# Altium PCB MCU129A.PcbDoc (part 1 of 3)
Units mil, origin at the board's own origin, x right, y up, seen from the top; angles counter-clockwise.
Board outline 3092.79 x 1702.62 mil, 4 copper layers (Top Layer, L2_GND, L3_PWR/SIG, Bottom Layer), stack 58.736 mil thick; 213 components, 108 nets, 914 pads, 219 vias.
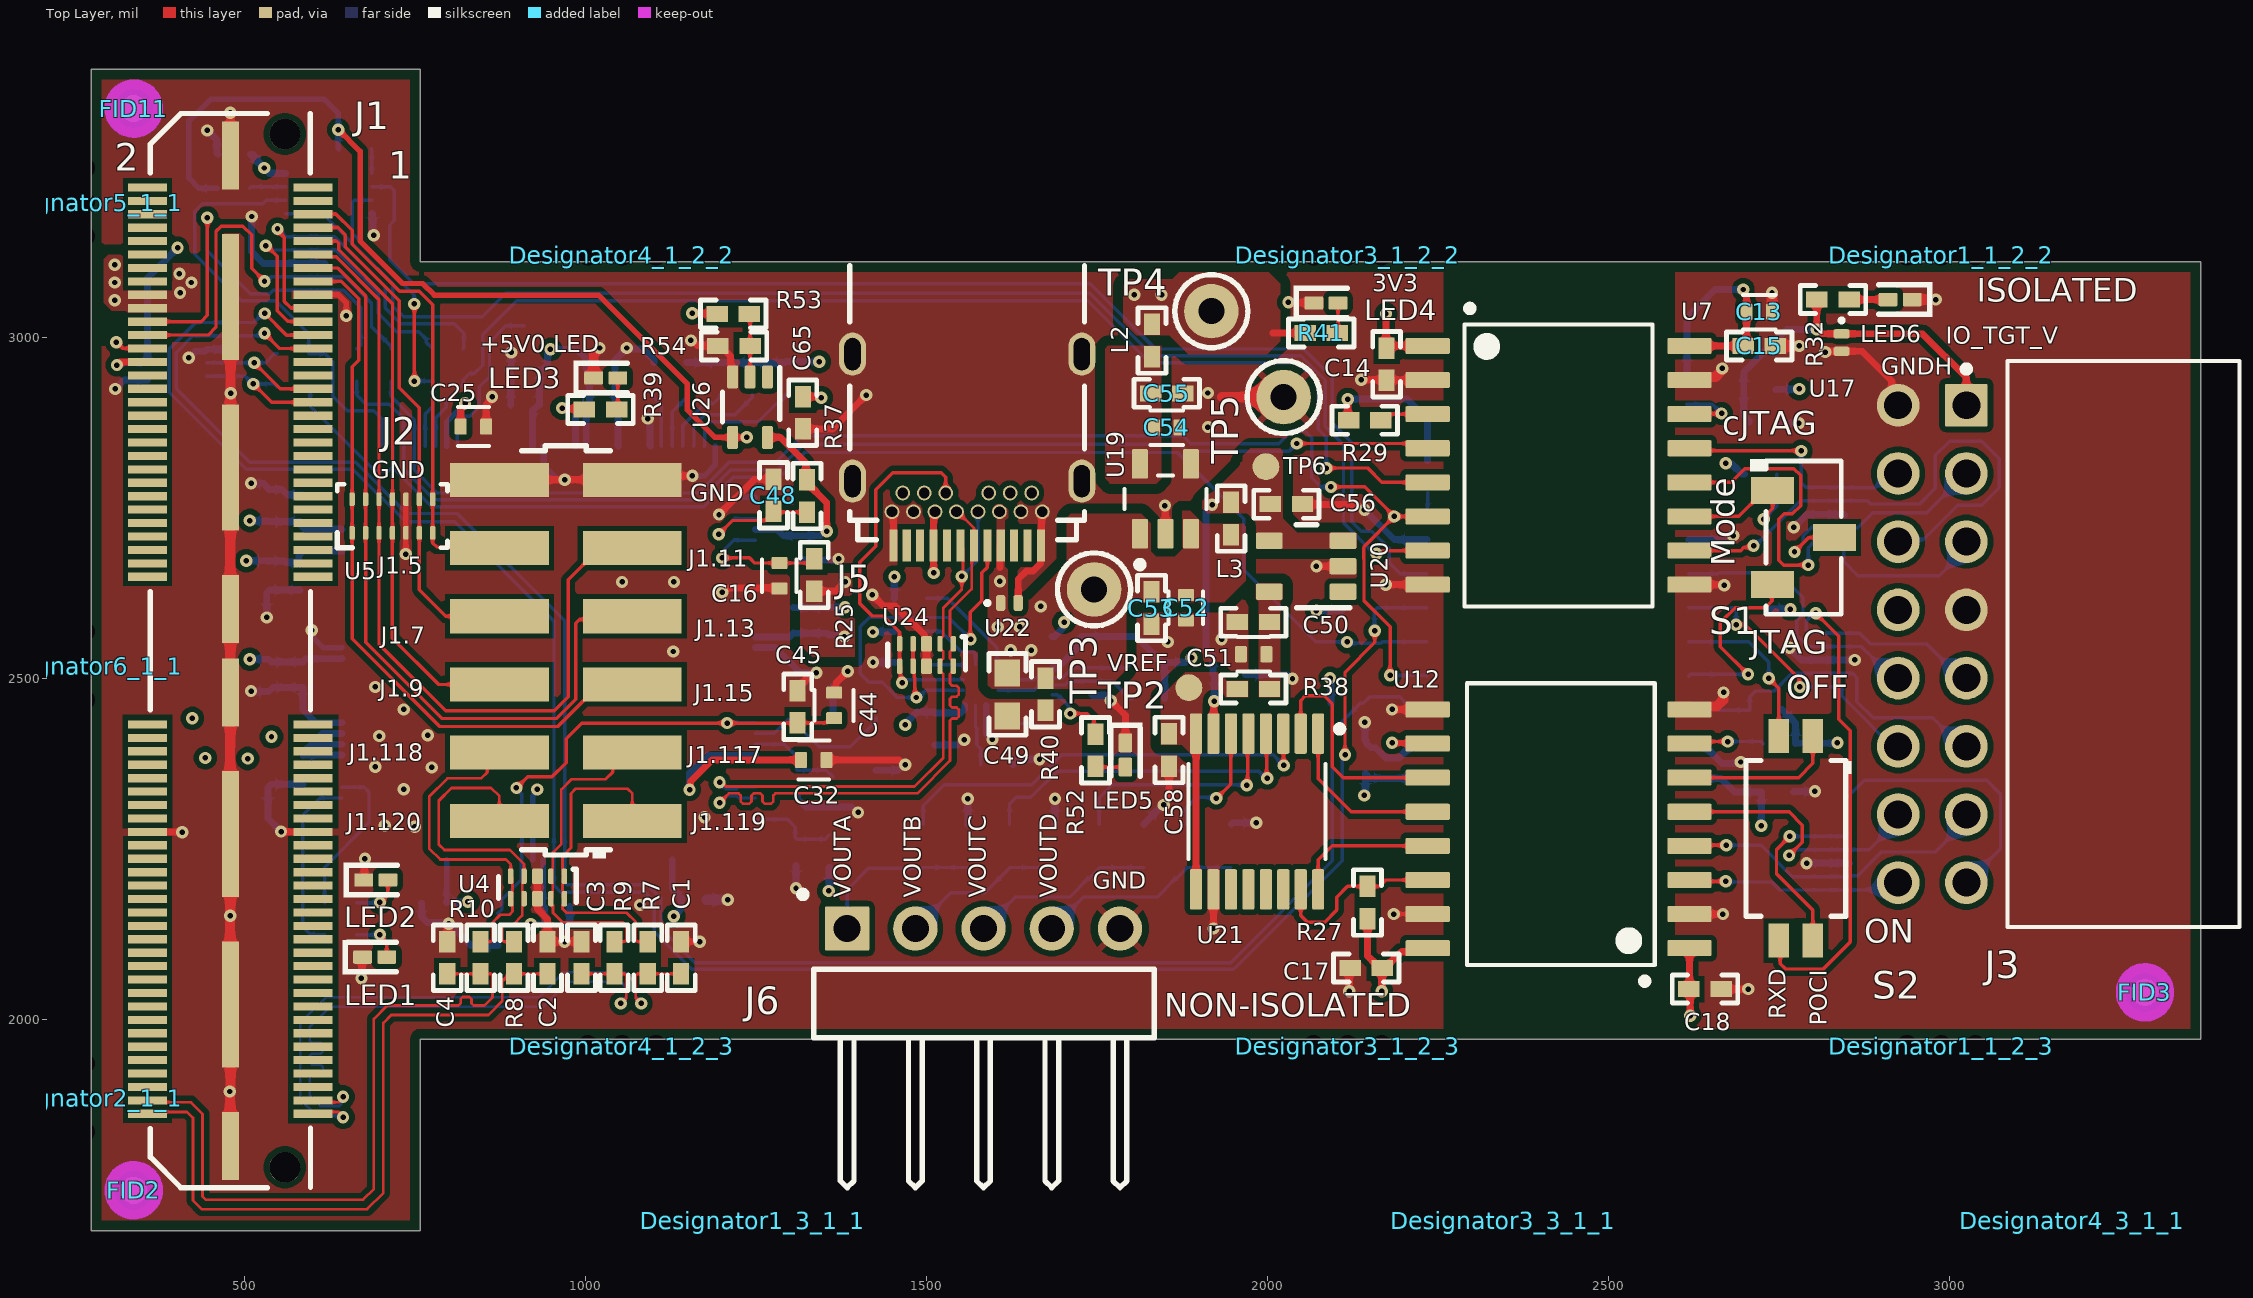
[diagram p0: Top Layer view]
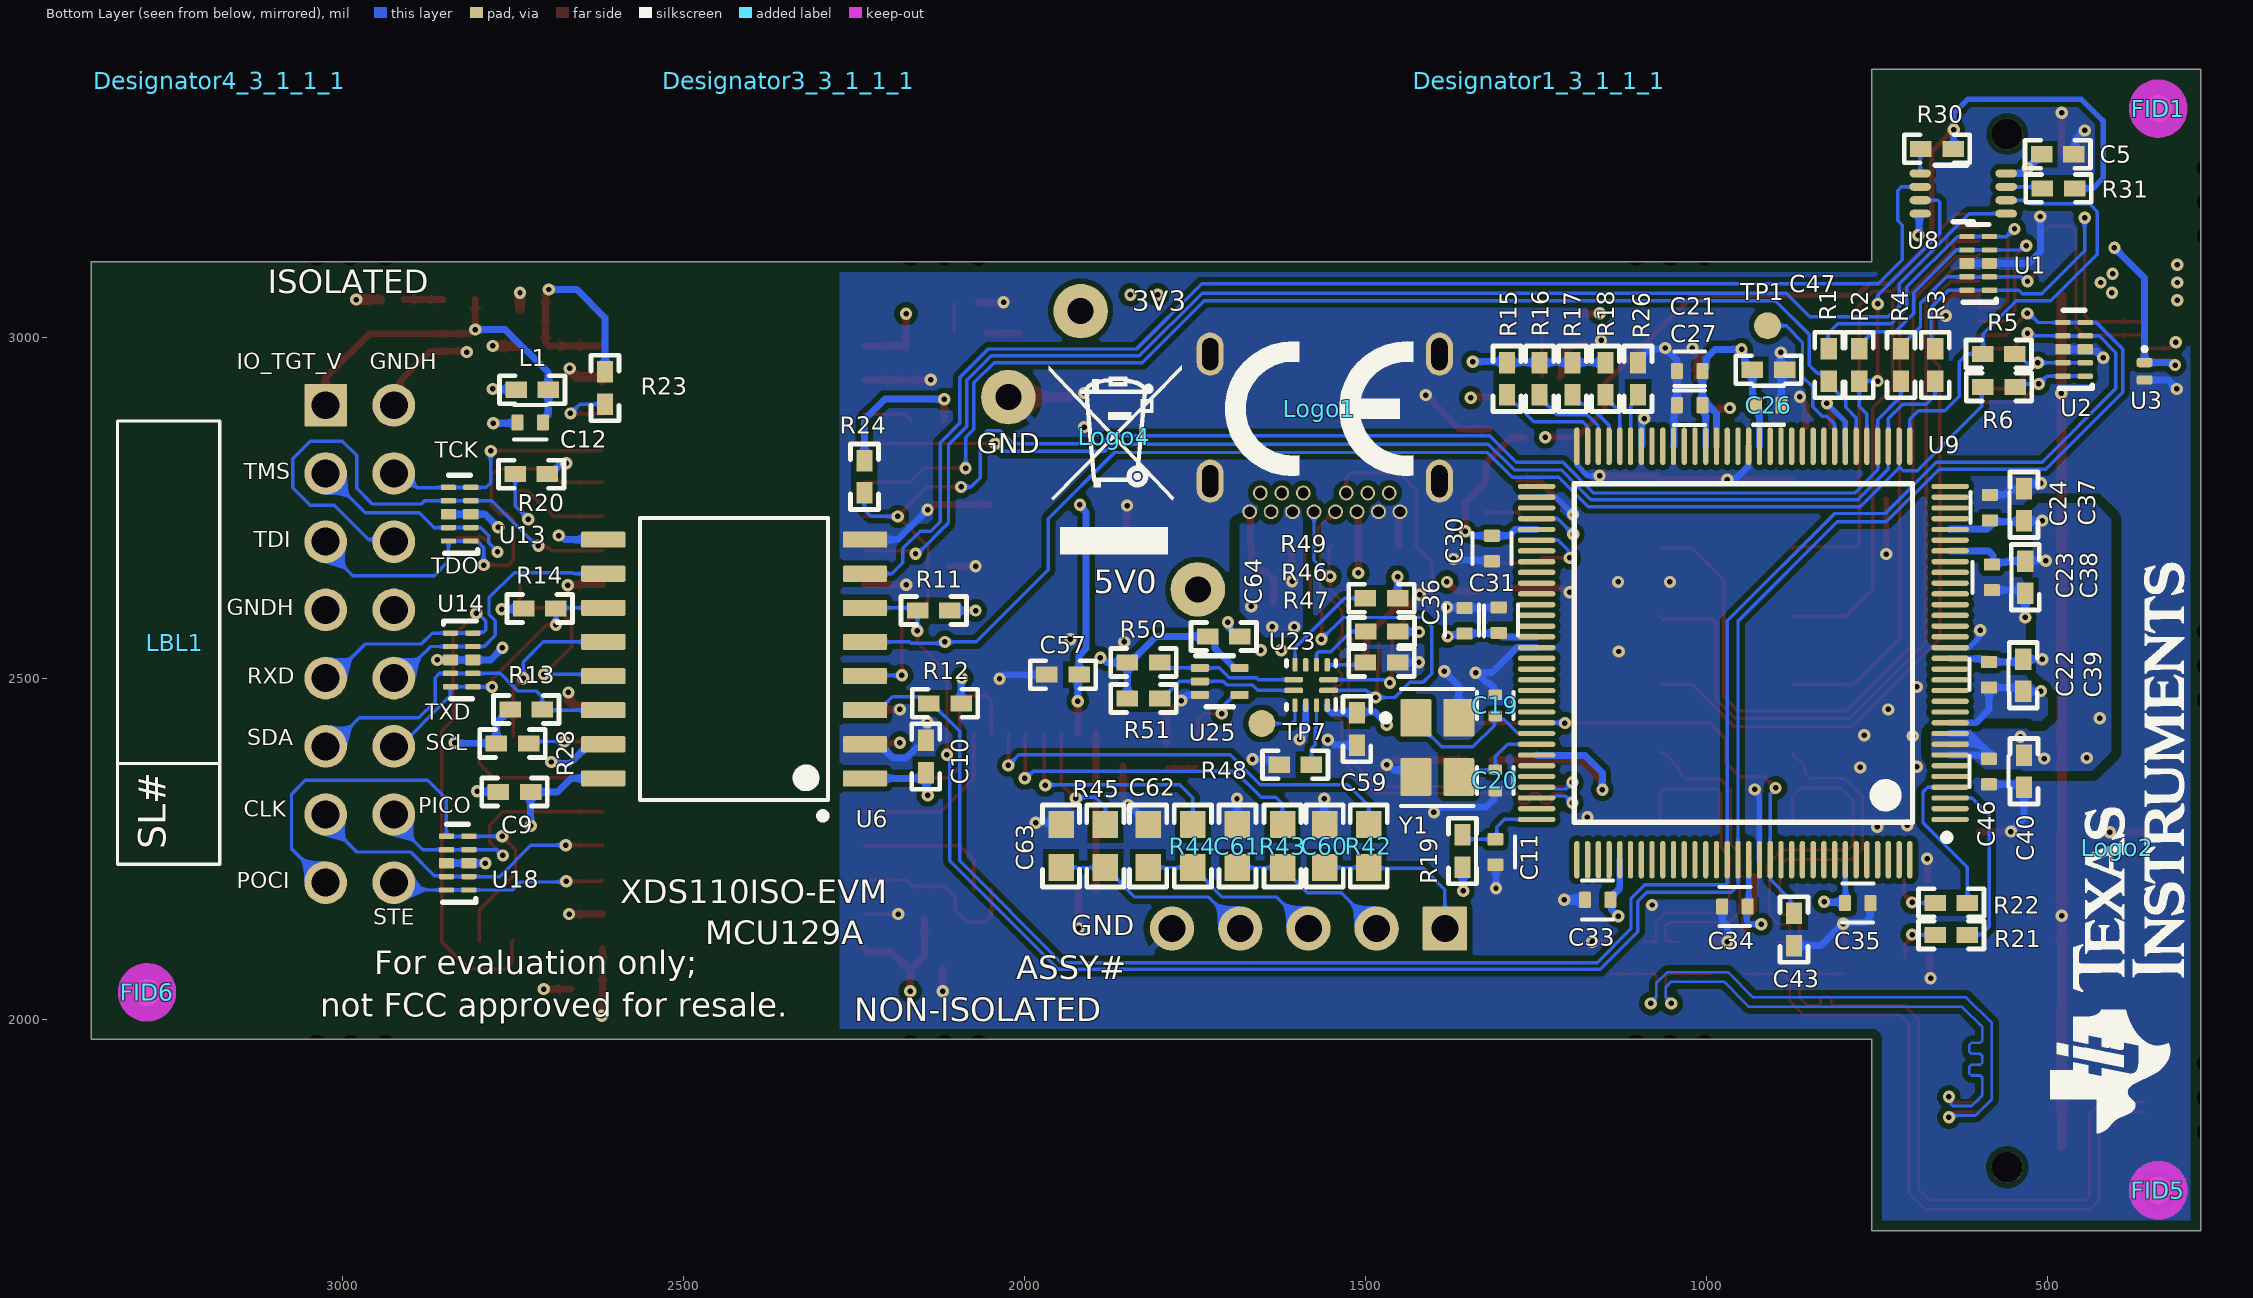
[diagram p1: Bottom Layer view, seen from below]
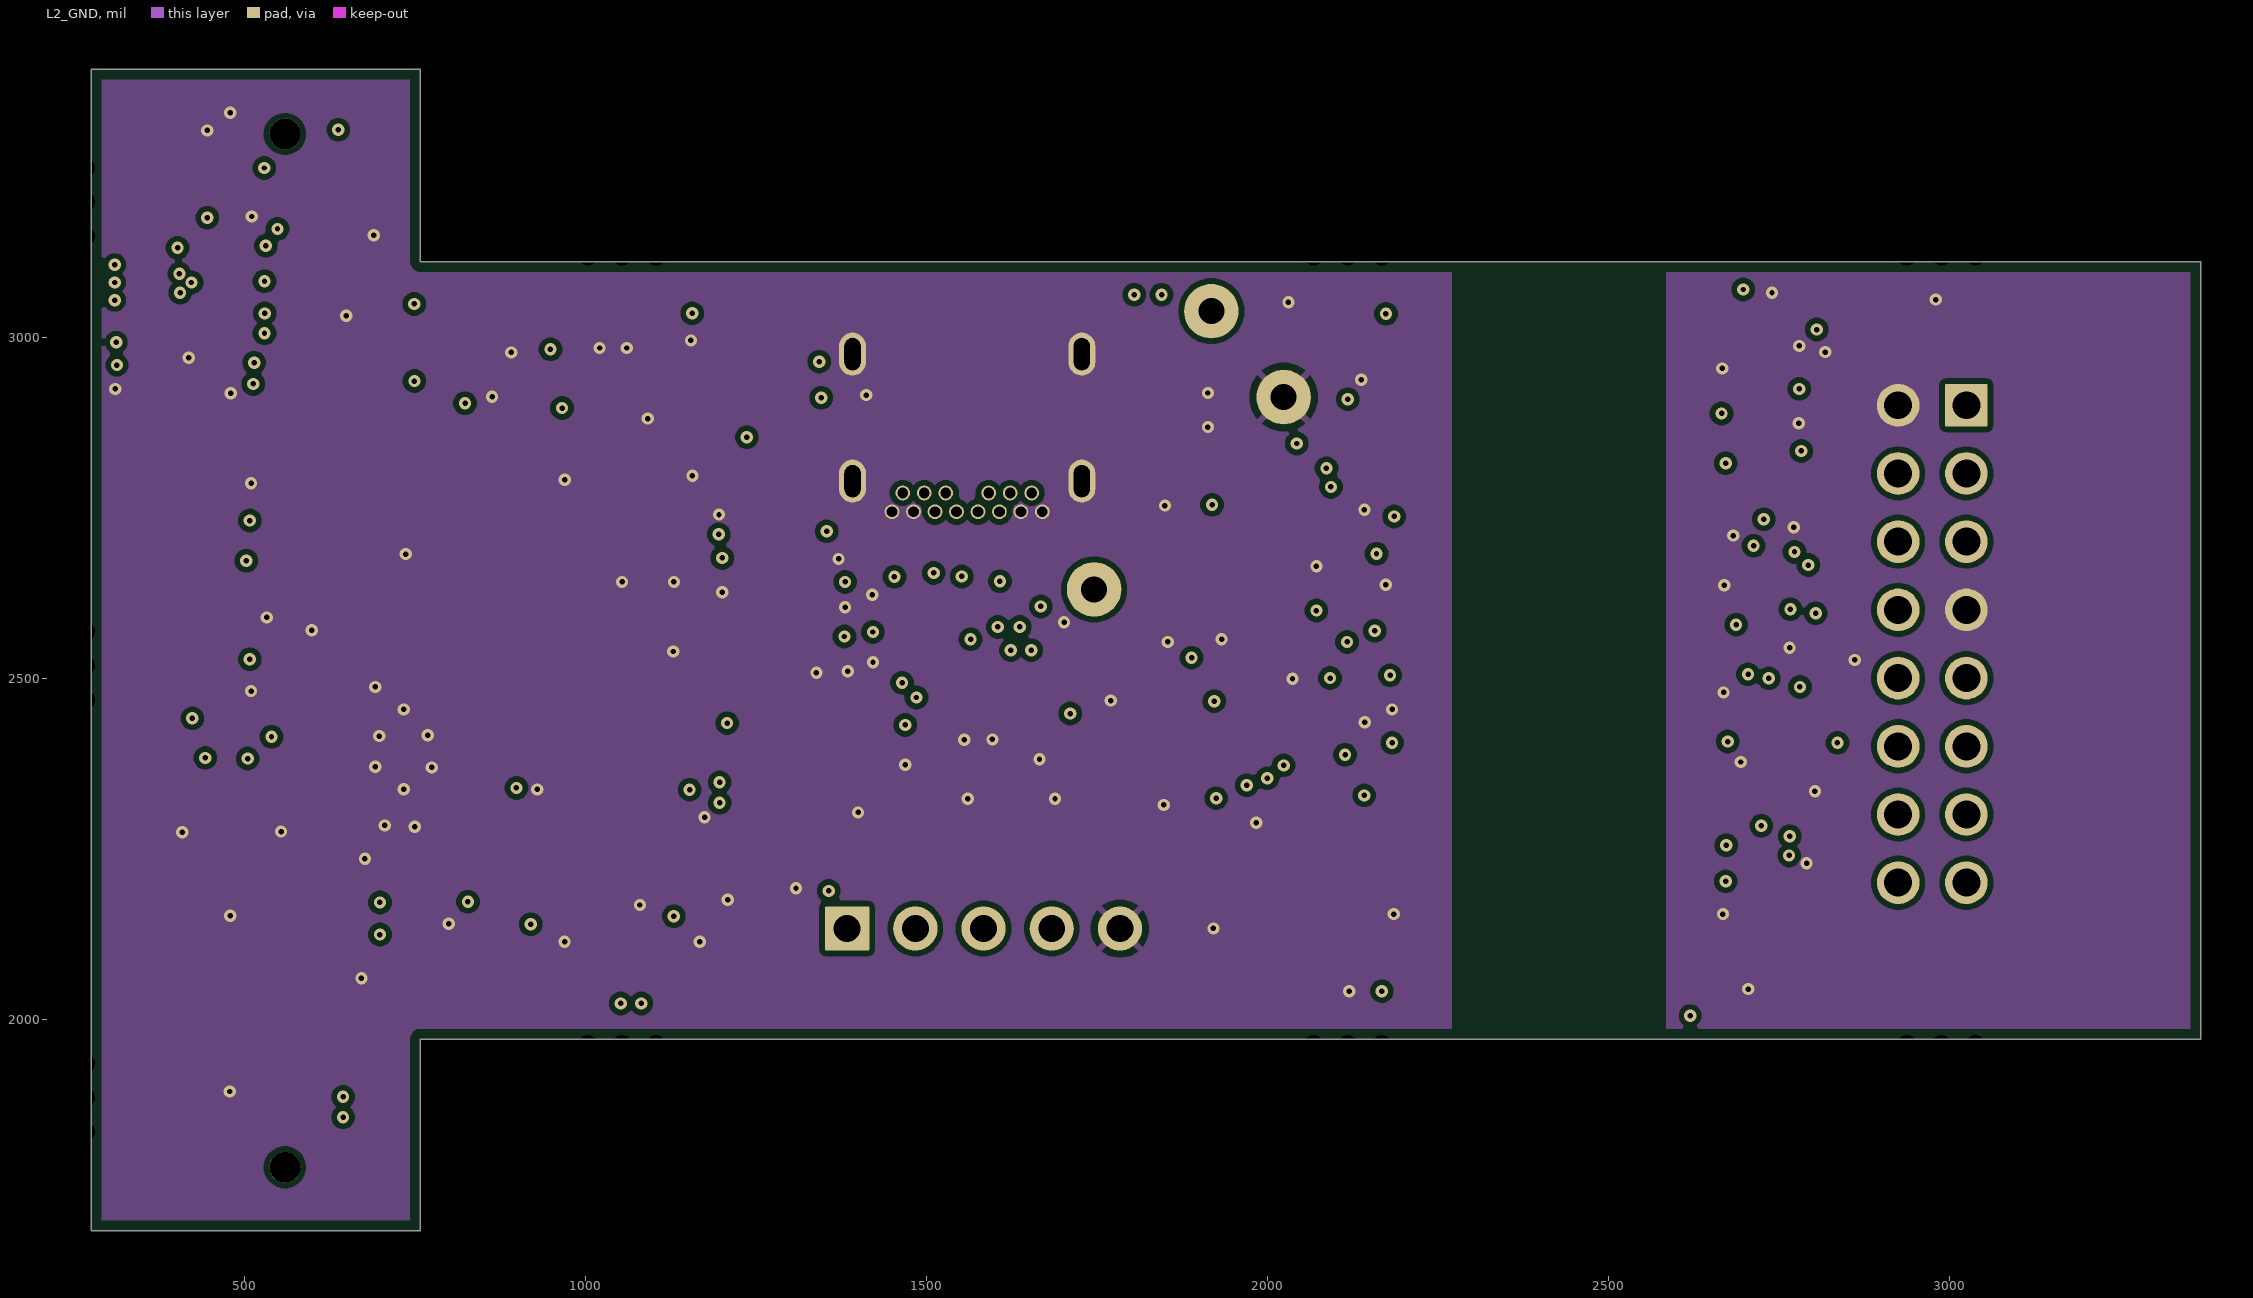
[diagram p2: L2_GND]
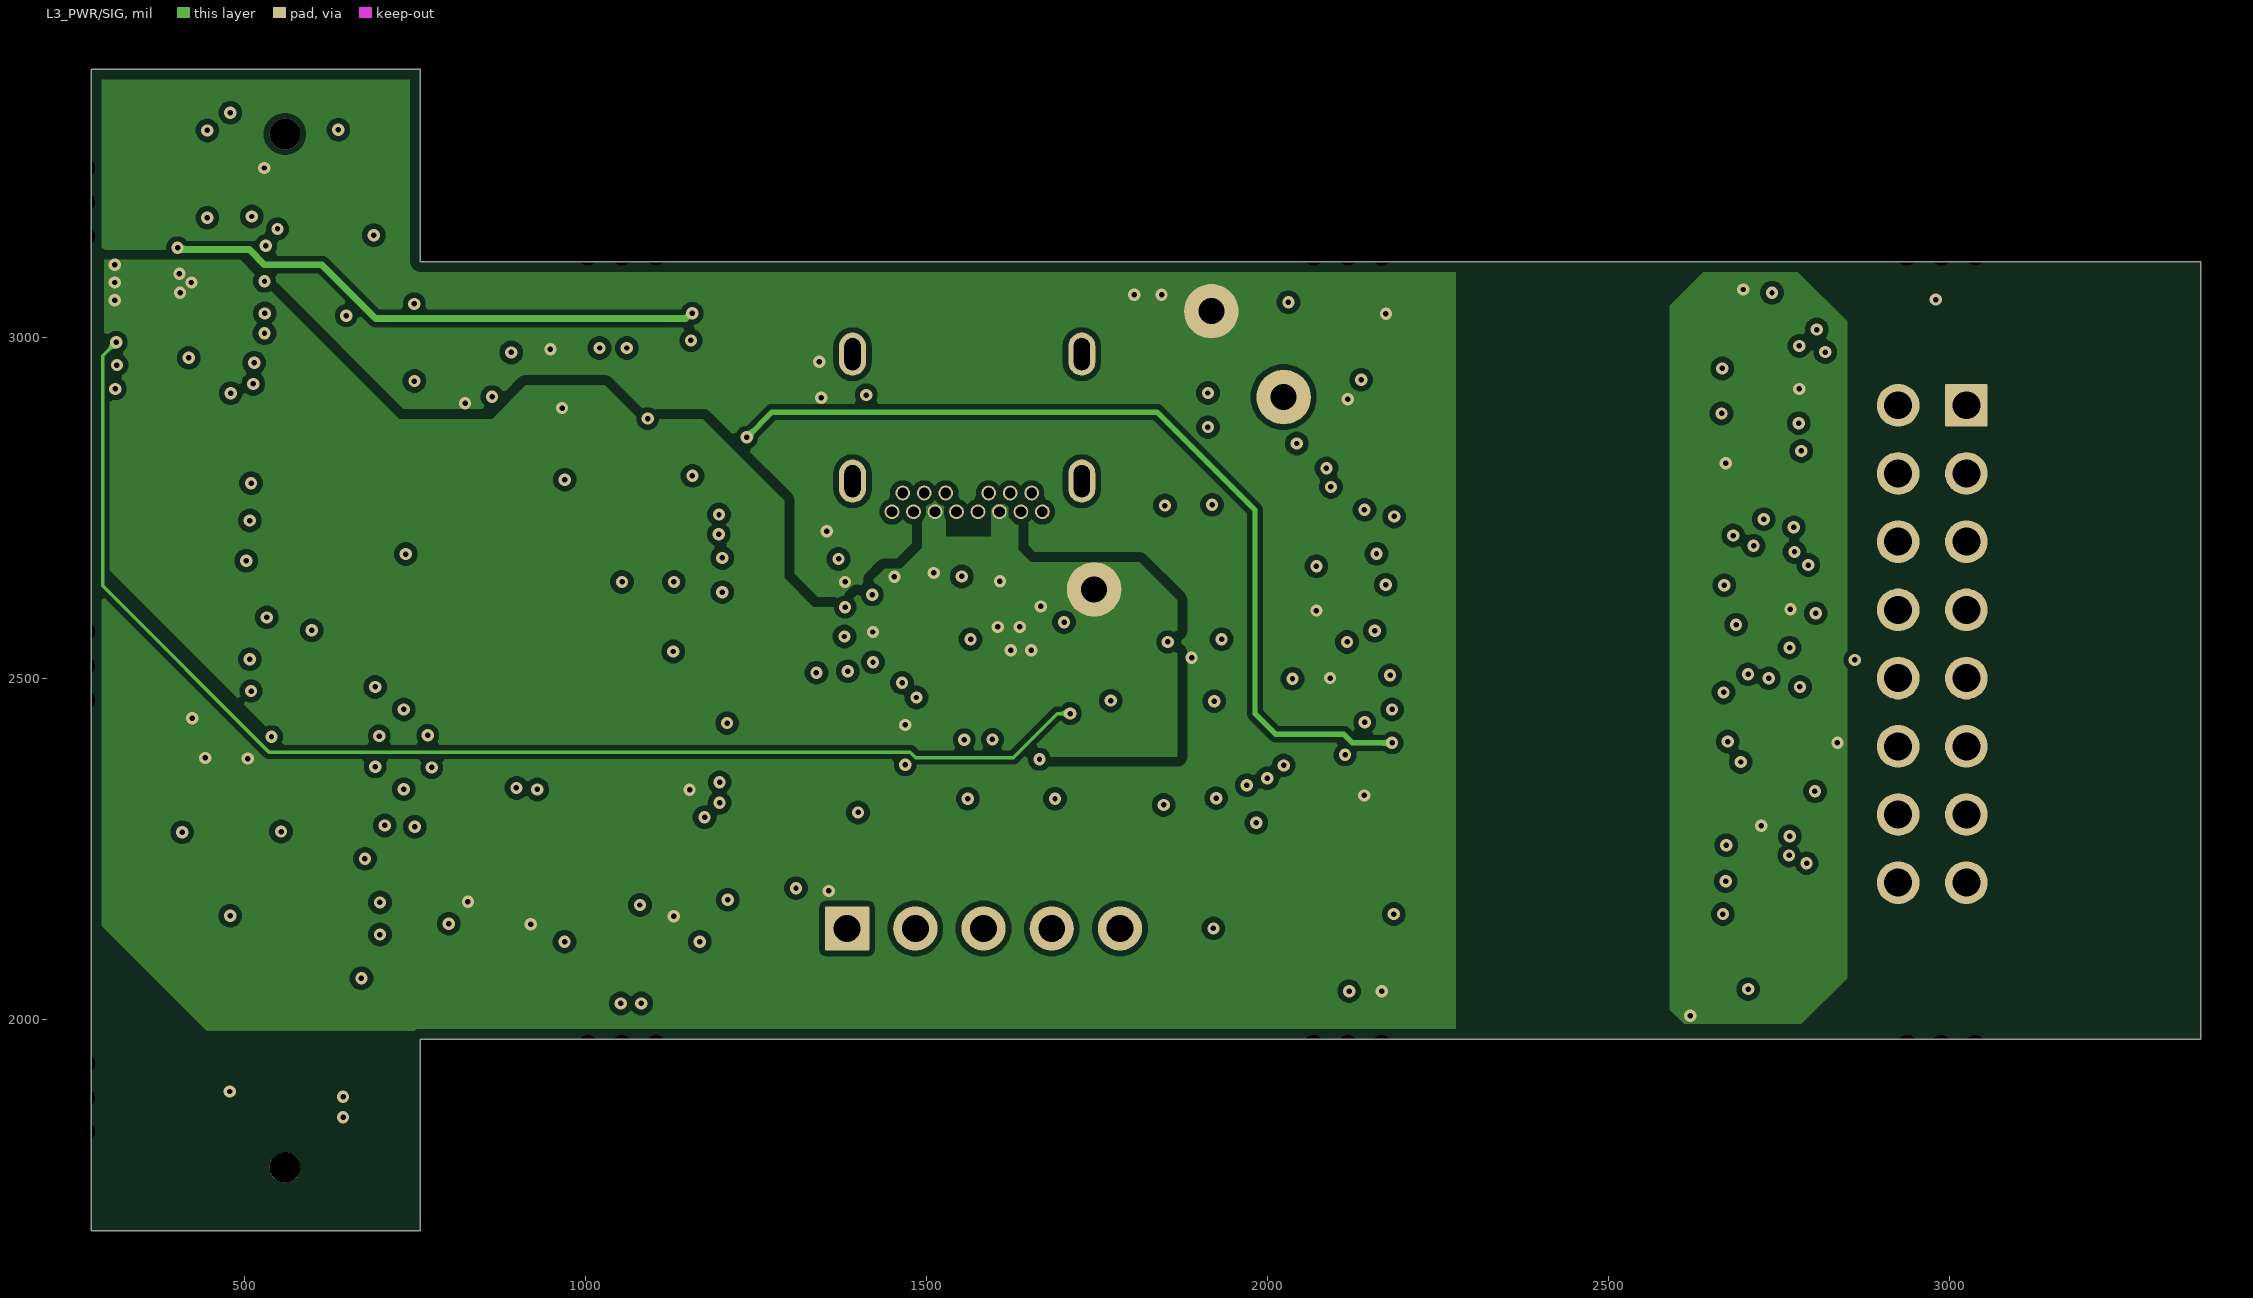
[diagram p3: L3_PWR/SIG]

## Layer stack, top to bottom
Top Solder: solder mask 1, Solder Resist, Dk 3.5
Top Layer: signal copper 1.968
Dielectric 2: prepreg 3.7, FR-4, Dk 4.1
L2_GND: signal copper 1.2
Dielectric 1: dielectric 45, FR-4, Dk 4.8
L3_PWR/SIG: signal copper 1.2
Dielectric 3: prepreg 3.7, FR-4, Dk 4.1
Bottom Layer: signal copper 1.968
Bottom Solder: solder mask 1, Solder Resist, Dk 3.5

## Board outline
275.59,1691.18 275.59,3393.8 757.95,3393.8 757.95,3111.85 3368.38,3111.85 3368.38,1971.84 757.95,1971.84 757.95,1691.18

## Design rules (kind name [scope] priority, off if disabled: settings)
AcuteAngle [All] p1: minimum=4.50000000000000E+0001 checktracksonly=TRUE
BoardOutlineClearance BoardOutlineClearance_1 [OnCopper and IsPoly] p1: gap=10 ignorepadtopadclearanceinfootprint=FALSE except(0: Arc-SplitContinuation Track-SplitContinuation SMDPad-SplitContinuation THPad-SplitContinuation Via-SplitContinuation Fill-SplitContinuation Poly-SplitContinuation Region-SplitContinuation Text-SplitContinuation; 15: Arc-OutlineEdge Arc-CavityEdge Track-OutlineEdge SMDPad-OutlineEdge THPad-OutlineEdge Via-OutlineEdge Fill-OutlineEdge Poly-OutlineEdge Region-OutlineEdge Text-OutlineEdge)
Clearance DIFF_90E_1 [InDifferentialPairClass('DIFF_90E') vs InDifferentialPairClass('DIFF_90E')] p1: gap=6 ignorepadtopadclearanceinfootprint=FALSE except(3: Arc-Via Track-Via; 12: Via-Via)
Clearance DIFF_100E [InDifferentialPairClass('DIFF_100E') vs InDifferentialPairClass('DIFF_100E')] p2: gap=6 ignorepadtopadclearanceinfootprint=FALSE except(5: Arc-Arc Arc-Track Track-Track; 12: Via-Via)
Clearance [All] p3: gap=8 ignorepadtopadclearanceinfootprint=FALSE except(0: Arc-Hole Track-Hole SMDPad-Hole THPad-Hole Via-Hole Fill-Hole Poly-Hole Region-Hole Text-Hole; 5: Arc-Arc Arc-Track Track-Track; 6: Arc-SMDPad Track-SMDPad Poly-Region Region-Region; 7: Arc-Via Track-Via SMDPad-SMDPad SMDPad-Via; 10: Via-Via; 15: Fill-Fill Fill-Poly Fill-Region Poly-Poly)
Clearance GND [InNet('GND') vs InNet('GNDH')] p4: gap=10 ignorepadtopadclearanceinfootprint=FALSE except(0: Arc-Hole Track-Hole SMDPad-Hole THPad-Hole Via-Hole Fill-Hole Poly-Hole Region-Hole Text-Hole; 7: Arc-Arc Arc-Track Track-Track; 8: SMDPad-SMDPad; 30: Poly-Poly)
ComponentClearance ComponentClearance_1 [HasFootprint('TESTPOINT')] p1: gap=0 collisioncheckmode=3 verticalgap=0 showdistances=FALSE
ComponentClearance [All] p2: gap=10 collisioncheckmode=3 verticalgap=6 showdistances=FALSE
DiffPairsRouting DIFF_100E_ANALOG_IN_1 [InDifferentialPairClass('DIFF_100E_ANALOG_IN')] p1: maxlimit=10 minlimit=5 mostfreqgap=10 toplayer_mingap=10 toplayer_minwidth=4 toplayer_maxwidth=4 toplayer_prefwidth=4 midlayer1_mingap=6 midlayer1_maxgap=6 midlayer1_prefgap=6 midlayer1_minwidth=4 midlayer1_maxwidth=4 midlayer1_prefwidth=4 midlayer2_maxgap=5 midlayer2_prefgap=5 midlayer2_minwidth=6 midlayer2_maxwidth=6 midlayer2_prefwidth=6 bottomlayer_mingap=10 bottomlayer_minwidth=4 bottomlayer_maxwidth=4 bottomlayer_prefwidth=4 maxuncoupledlength=500
DiffPairsRouting Diff_90E [InDifferentialPairClass('DIFF_90E')] p2: maxlimit=6 minlimit=6 mostfreqgap=6 toplayer_minwidth=4 toplayer_maxwidth=4 toplayer_prefwidth=4 midlayer1_minwidth=4 midlayer1_maxwidth=4 midlayer1_prefwidth=4 midlayer2_minwidth=4 midlayer2_maxwidth=4 midlayer2_prefwidth=4 bottomlayer_minwidth=4 bottomlayer_maxwidth=4 bottomlayer_prefwidth=4 maxuncoupledlength=500
DiffPairsRouting DiffPair_DIFF_100EDiffPairsRouting [InDifferentialPairClass('DIFF_100E')] p3: maxlimit=10 minlimit=5 mostfreqgap=10 toplayer_mingap=10 toplayer_minwidth=4 toplayer_maxwidth=4 toplayer_prefwidth=4 midlayer1_mingap=6 midlayer1_maxgap=6 midlayer1_prefgap=6 midlayer1_minwidth=4 midlayer1_maxwidth=4 midlayer1_prefwidth=4 midlayer2_maxgap=5 midlayer2_prefgap=5 midlayer2_minwidth=6 midlayer2_maxwidth=6 midlayer2_prefwidth=6 bottomlayer_mingap=10 bottomlayer_minwidth=4 bottomlayer_maxwidth=4 bottomlayer_prefwidth=4 maxuncoupledlength=500
HoleSize [All] p1: absolutevalues=TRUE maxlimit=200 minlimit=1 maxpercent=80.000 minpercent=20.000
MatchedLengths DIFF_100E_ANALOG_IN [InDifferentialPairClass('DIFF_100E_ANALOG_IN')] p1: tolerance=30 checknetsindiffpair=FALSE checkdiffpairvsdiffpair=TRUE checkxsignals=TRUE checkothers=TRUE
MatchedLengths DIFF_100E_ANALOG_IN_MATCHEDLENGTH_ANALOG_IN [InDifferentialPairClass('DIFF_100E_ANALOG_IN')] p2: tolerance=2 checknetsindiffpair=TRUE checkdiffpairvsdiffpair=FALSE checkxsignals=FALSE checkothers=FALSE
MatchedLengths MatchedLength_DIFF_90E [InDifferentialPairClass('DIFF_90E')] p3: tolerance=2 checknetsindiffpair=TRUE checkdiffpairvsdiffpair=FALSE checkxsignals=FALSE checkothers=FALSE
MatchedLengths MatchedLengths_DIFF_100E [InDifferentialPairClass('DIFF_100E')] p4: tolerance=5 checknetsindiffpair=TRUE checkdiffpairvsdiffpair=FALSE checkxsignals=FALSE checkothers=FALSE
MatchedLengths DIFF_100E_GRP [InDifferentialPairClass('DIFF_100E')] p5: tolerance=20 checknetsindiffpair=FALSE checkdiffpairvsdiffpair=TRUE checkxsignals=TRUE checkothers=TRUE
MinimumSolderMaskSliver Silk_SOLD-Exclusion [HasFootprint('WURTH_632_723_300_011') OR HasFootprint('DQA0010A') OR HasFootprint('DBV0005A_N') OR HasFootprint('RWB0012A') OR HasFootprint('RVZ0014A') OR HasFootprint('DCK0005A_N') OR HasFootprint('SAMTEC_QTH-060-01-L-D-A')] p1: minsoldermaskwidth=0.3
MinimumSolderMaskSliver [All] p2: minsoldermaskwidth=1.1
PolygonConnect [All] p1: connectstyle=Direct reliefconductorwidth=10 reliefentries=4 polygonreliefangle="90 Angle" airgapwidth=10
RoutingVias [All] p1: holewidth=8 width=18 viastyle="Through Hole" minholewidth=8 minwidth=18 maxholewidth=8 maxwidth=18
SilkToSolderMaskClearance silk-sold_c [HasFootprint('RVZ0014A')] p1: minsilkscreentomaskgap=0 clearancetoexposedcopper=TRUE
SilkToSolderMaskClearance SilkSOLD_Exception [(HasFootprint('0402') OR HasFootprint('DCK0005A_N') OR HasFootprint('RWB0012A') OR HasFootprint('0603') OR HasFootprint('PDT0128A') OR HasFootprint('RVZ0014A') OR HasFootprint('Samtec_TSM-106-01-x-DV') OR HasFootprint('DQA0010A'))] p2: minsilkscreentomaskgap=0.3 clearancetoexposedcopper=TRUE
SilkToSolderMaskClearance [IsPad] p3: minsilkscreentomaskgap=6 clearancetoexposedcopper=TRUE
SolderMaskExpansion [All] p1: expansion=4 istentingtop=FALSE
Width Power [InNetClass('power')] p1: maxlimit=20 minlimit=10 preferedwidth=10 minimp=50.000000 maximp=50.000000 favimp=50.000000
Width [All] p2: maxlimit=15 minlimit=5 preferedwidth=10 toplayer_prefwidth=5 midlayer1_minwidth=10 midlayer2_prefwidth=5 bottomlayer_prefwidth=5 minimp=50.000000 maximp=50.000000 favimp=50.000000
25 further rules are at their usual default settings.

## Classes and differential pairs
differential pair class DIFF_100E: A_IN1 A_IN3
differential pair class DIFF_90E: USB_D
differential pair class DIFF_1OOE_ANALOG_IN: ANALOG_IN_B NALOG_IN_A
differential pair A_IN3: +A_IN5_CONN -A_IN6_CONN
differential pair A_IN1: +A_IN1_CONN -A_IN2_CONN
differential pair USB_D: +USB_D_P -USB_D_N
differential pair ANALOG_IN_B: +ANALOG_IN_6 -ANALOG_IN_5
differential pair NALOG_IN_A: +ANALOG_IN_2 -ANALOG_IN_1

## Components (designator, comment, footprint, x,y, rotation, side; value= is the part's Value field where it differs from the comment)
C1 "GRM1555C1H331JA01D" 0402 1140.46,2091.18 r270 top value=330pF
C2 "GRM1555C1H331JA01D" 0402 944.46,2091.18 r90 top value=330pF
C3 "GRM1555C1H331JA01D" 0402 994.46,2091.18 r90 top value=330pF
C4 "GRM1555C1H331JA01D" 0402 797.46,2091.18 r90 top value=330pF
C5 "GRM155R71E104KE14D" 0402 485.19,3269.18 r0 bottom value=0.1uF
C9 "GRM155R71E104KE14D" 0402 2747.81,2334.18 r180 bottom value=0.1uF
C10 "GRM155R71E104KE14D" 0402 2144.81,2386.18 r90 bottom value=0.1uF
C11 "GRM1555C1E103JE01D" FP-GRM1555C1E103JE01D_0402-MFG 1309.81,2246.18 r90 bottom value=10nF
C12 "GRM155C61E475ME15D" FP-GRM155C61E475ME15D_0402-MFG 2724.81,2876.18 r180 bottom value=4.7µF
C13 "GRM155C61E475ME15D" FP-GRM155C61E475ME15D_0402-MFG 2721.19,3038.18 r180 top value=4.7µF
C14 "GRM155R71E104KE14D" 0402 2174.81,2961.18 r270 top value=0.1uF
C15 "GRM155R71E104KE14D" 0402 2721.19,2988.18 r180 top value=0.1uF
C16 "GRM155R61A106ME18D" FP-GRM155R61A106ME18D_0402-MFG 1284.81,2651.18 r90 top value=10µF
C17 "GRM155R71E104KE14D" 0402 2144.81,2076.18 r180 top value=0.1uF
C18 "GRM155R71E104KE14D" 0402 2641.43,2045.18 r180 top value=0.1uF
C19 "GRT1555C1H120JA02D" FP-GRT1555C1H120JA02D_0402-MFG 1309.81,2461.18 r270 bottom value=12pF
C20 "GRT1555C1H120JA02D" FP-GRT1555C1H120JA02D_0402-MFG 1309.81,2351.18 r90 bottom value=12pF
C21 "GRM1555C1E103JE01D" FP-GRM1555C1E103JE01D_0402-MFG 1024.81,2951.18 r180 bottom value=10nF
C22 "GRM1555C1E103JE01D" FP-GRM1555C1E103JE01D_0402-MFG 585.81,2506.18 r90 bottom value=10nF
C23 "GRM1555C1E103JE01D" FP-GRM1555C1E103JE01D_0402-MFG 581.81,2648.94 r90 bottom value=10nF
C24 "GRM1555C1E103JE01D" FP-GRM1555C1E103JE01D_0402-MFG 584.81,2751.18 r270 bottom value=10nF
C25 "GRM1555C1E103JE01D" FP-GRM1555C1E103JE01D_0402-MFG 835.83,2869.83 r180 top value=10nF
C26 "GRM1555C1E103JE01D" FP-GRM1555C1E103JE01D_0402-MFG 909.19,2901.18 r0 bottom value=10nF
C27 "GRM1555C1E103JE01D" FP-GRM1555C1E103JE01D_0402-MFG 1024.81,2901.18 r180 bottom value=10nF
C30 "GRM1555C1E103JE01D" FP-GRM1555C1E103JE01D_0402-MFG 1314.81,2691.18 r90 bottom value=10nF
C31 "GRM1555C1E103JE01D" FP-GRM1555C1E103JE01D_0402-MFG 1304.81,2586.18 r270 bottom value=10nF
C32 "GRM1555C1E103JE01D" FP-GRM1555C1E103JE01D_0402-MFG 1334.81,2381.18 r180 top value=10nF
C33 "GRM1555C1E103JE01D" FP-GRM1555C1E103JE01D_0402-MFG 1159.81,2176.18 r180 bottom value=10nF
C34 "GRM1555C1E103JE01D" FP-GRM1555C1E103JE01D_0402-MFG 958.51,2166.18 r180 bottom value=10nF
C35 "GRM1555C1E103JE01D" FP-GRM1555C1E103JE01D_0402-MFG 778.51,2171.18 r0 bottom value=10nF
C36 "GRM1555C1E103JE01D" FP-GRM1555C1E103JE01D_0402-MFG 1354.81,2585.18 r270 bottom value=10nF
C37 "GRM155R61E105KE11D" 0402 534.81,2755.18 r90 bottom value=1uF
C38 "GRM155R61E105KE11D" 0402 532.81,2649.18 r270 bottom value=1uF
C39 "GRM155R61E105KE11D" 0402 535.81,2505.18 r270 bottom value=1uF
C40 "GRM155R61E105KE11D" 0402 534.81,2364.56 r270 bottom value=1uF
C43 "GRM155R61E105KE11D" 0402 871.81,2132.56 r270 bottom value=1uF
C44 "GRM1555C1E103JE01D" FP-GRM1555C1E103JE01D_0402-MFG 1364.81,2461.18 r270 top value=10nF
C45 "GRM155R61E225ME15D" 0402 1311.31,2459.18 r90 top value=2.2uF
C46 "GRM1555C1E103JE01D" FP-GRM1555C1E103JE01D_0402-MFG 586.05,2364.19 r90 bottom value=10nF
C47 "GRM155R61E105KE11D" 0402 909.19,2953.18 r180 bottom value=1uF
C48 "GRM155R71E104KE14D" 0402 1275.73,2769.16 r270 top value=0.1uF
C49 "GRM188R61C106MAALD" 0603 1618.85,2477.2 r270 top value=10uF
C50 "GRM155R71A473KA01D" 0402 1979.43,2583.18 r180 top value=0.047uF
C51 "GRM155C61E475ME15D" FP-GRM155C61E475ME15D_0402-MFG 1979.81,2536.18 r0 top value=4.7µF
C52 "GRM155C61E475ME15D" FP-GRM155C61E475ME15D_0402-MFG 1880.64,2604.31 r90 top value=4.7µF
C53 "GRM155R71E104KE14D" 0402 1829.99,2603.93 r90 top value=0.1uF
C54 "GRM155C61E475ME15D" FP-GRM155C61E475ME15D_0402-MFG 1852.31,2868.68 r180 top value=4.7µF
C55 "GRM155R71E104KE14D" 0402 1852.31,2918.68 r180 top value=0.1uF
C56 "GRM155R71E104KE14D" 0402 2027.81,2756.18 r0 top value=0.1uF
C57 "GRM155R71E104KE14D" 0402 1943.81,2506.18 r180 bottom value=0.1uF
C58 "GRM155R71E104KE14D" 0402 1855.67,2395.74 r90 top value=0.1uF
C59 "GRM155R71E104KE14D" 0402 1512.81,2426.56 r90 bottom value=0.1uF
C60 "GRM1885C1H103JA01D" 0603 1560.09,2254.99 r90 bottom value=0.01uF
C61 "GRM1885C1H103JA01D" 0603 1687.84,2254.99 r90 bottom value=0.01uF
C62 "GRM1885C1H103JA01D" 0603 1818.83,2254.99 r90 bottom value=0.01uF
C63 "GRM1885C1H103JA01D" 0603 1946.54,2254.99 r90 bottom value=0.01uF
C64 "GRM155R71E104KE14D" 0402 1707.81,2562.18 r0 bottom value=0.1uF
C65 "GRM155R71E104KE14D" 0402 1318.81,2890.18 r90 top value=0.1uF
Designator1_1_2_2 "Comment" BRAKE_WAY_HOLES1X3 2987.92,3151.22 r180 top
Designator1_1_2_2_1 "Comment" BRAKE_WAY_HOLES1X3 2987.91,5982.4 r180 top
Designator1_1_2_3 "Comment" BRAKE_WAY_HOLES1X3 2987.92,1932.48 r0 top
Designator1_1_2_3_1 "Comment" BRAKE_WAY_HOLES1X3 2987.91,4763.66 r0 top
Designator1_1_2_4 "Comment" BRAKE_WAY_HOLES1X3 3158.87,516.88 r0 top
Designator1_1_2_5 "Comment" BRAKE_WAY_HOLES1X3 4002.75,1770.1 r90 top
Designator1_1_2_5_1 "Comment" BRAKE_WAY_HOLES1X3 4002.75,4601.29 r90 top
Designator1_1_2_7 "Comment" BRAKE_WAY_HOLES1X3 4002.75,545.05 r90 top
Designator1_1_2_7_1 "Comment" BRAKE_WAY_HOLES1X3 4002.75,3376.23 r90 top
Designator1_1_2_8 "Comment" BRAKE_WAY_HOLES1X3 4002.75,1128.72 r90 top
Designator1_1_2_8_1 "Comment" BRAKE_WAY_HOLES1X3 4002.75,3959.9 r90 top
Designator1_3_1_1 "Comment" BRAKE_WAY_HOLES1X3 1245.32,1735.63 r180 top
Designator1_3_1_1_1 "Comment" BRAKE_WAY_HOLES1X3 1245.32,3348.06 r180 bottom
Designator1_3_1_1_2 "Comment" BRAKE_WAY_HOLES1X3 1245.32,4566.81 r180 top
Designator2_1 "Comment" BRAKE_WAY_HOLES1X3 235.44,4717.17 r270 top
Designator2_1_1 "Comment" BRAKE_WAY_HOLES1X3 235.44,1885.98 r270 top
Designator3_1_2_2 "Comment" BRAKE_WAY_HOLES1X3 2117.7,3151.22 r180 top
Designator3_1_2_2_1 "Comment" BRAKE_WAY_HOLES1X3 2117.69,5982.4 r180 top
Designator3_1_2_3 "Comment" BRAKE_WAY_HOLES1X3 2117.69,1932.48 r0 top
Designator3_1_2_3_1 "Comment" BRAKE_WAY_HOLES1X3 2117.69,4763.66 r0 top
Designator3_1_2_4 "Comment" BRAKE_WAY_HOLES1X3 2288.65,516.88 r0 top
Designator3_3_1_1 "Comment" BRAKE_WAY_HOLES1X3 2345.54,1735.63 r180 top
Designator3_3_1_1_1 "Comment" BRAKE_WAY_HOLES1X3 2345.54,3348.06 r180 bottom
Designator3_3_1_1_2 "Comment" BRAKE_WAY_HOLES1X3 2345.54,4566.81 r180 top
Designator4_1_2_2 "Comment" BRAKE_WAY_HOLES1X3 1053.49,3151.22 r180 top
Designator4_1_2_2_1 "Comment" BRAKE_WAY_HOLES1X3 1053.49,5982.4 r180 top
Designator4_1_2_3 "Comment" BRAKE_WAY_HOLES1X3 1053.49,1932.48 r0 top
Designator4_1_2_3_1 "Comment" BRAKE_WAY_HOLES1X3 1053.49,4763.66 r0 top
Designator4_1_2_4 "Comment" BRAKE_WAY_HOLES1X3 1224.45,516.88 r0 top
Designator4_3_1_1 "Comment" BRAKE_WAY_HOLES1X3 3179.74,1735.63 r180 top
Designator4_3_1_1_1 "Comment" BRAKE_WAY_HOLES1X3 3179.74,3348.06 r180 bottom
Designator4_3_1_1_2 "Comment" BRAKE_WAY_HOLES1X3 3179.74,4566.81 r180 top
Designator5_1 "Comment" BRAKE_WAY_HOLES1X3 235.44,6030.18 r270 top
Designator5_1_1 "Comment" BRAKE_WAY_HOLES1X3 235.44,3199 r270 top
Designator6_1 "Comment" BRAKE_WAY_HOLES1X3 235.44,5350.48 r270 top
Designator6_1_1 "Comment" BRAKE_WAY_HOLES1X3 235.44,2519.29 r270 top
FID1 "Fiducial" FIDUCIAL10-20 337.81,3336.18 r90 bottom
FID2 "Fiducial" FIDUCIAL10-20 337.81,1750.18 r90 top
FID3 "Fiducial" FIDUCIAL10-20 3286.63,2040.35 r90 top
FID5 "Fiducial" FIDUCIAL10-20 337.81,1750.18 r90 bottom
FID6 "Fiducial" FIDUCIAL10-20 3286.63,2040.35 r90 bottom
FID7 "Fiducial" FIDUCIAL10-20 317.52,6382.89 r90 top
FID8 "Fiducial" FIDUCIAL10-20 3919.89,6382.89 r270 top
FID9 "Fiducial" FIDUCIAL10-20 3919.7,117.49 r270 top
FID10 "Fiducial" FIDUCIAL10-20 327.94,117.69 r90 top
FID11 "Fiducial" FIDUCIAL10-20 337.81,3336.18 r90 top
FID12 "Fiducial" FIDUCIAL10-20 317.52,6382.89 r270 bottom
FID13 "Fiducial" FIDUCIAL10-20 3919.89,6382.89 r90 bottom
FID14 "Fiducial" FIDUCIAL10-20 3919.7,117.5 r90 bottom
FID15 "Fiducial" FIDUCIAL10-20 327.94,117.68 r270 bottom
J1 "QTH-060-01-L-D-A" SAMTEC_QTH-060-01-L-D-A 479.49,2541.45 r270 top locked
J2 "TSM-106-01-L-DV" Samtec_TSM-106-01-x-DV 971.37,2541.83 r180 top
J3 "SSW-108-02-G-D-RA-008" FP-SSW-108-02-G-D-RA-008_CONN_RCPT15-MFG 3252.33,2551.18 r270 top
J5 "632723300011" WURTH_632_723_300_011 1559.82,3112.03 r180 top locked
J6 "TSW-105-08-G-S-RA" TSW-105-08-G-S-RA 1583.81,2134.03 r0 top locked
L1 "BLM15BD121SN1D" 0402 2721.93,2923.99 r0 bottom value="120 ohm"
L2 "BLM15AG100SN1D" 0402 1830.81,2996.18 r90 top value="10 ohm"
L3 "BLM15AG100SN1D" 0402 1946.81,2735.18 r90 top value="10 ohm"
LBL1 "THT-14-423-10" LABEL_650X200 3245.81,2553.18 r90 bottom
LED1 "APHHS1005CGCK" APHHS1005_GREEN 691.09,2092.18 r180 top value=Green
LED2 "APHHS1005CGCK" APHHS1005_GREEN 692.81,2205.18 r180 top value=Green
LED3 "APHHS1005SURCK" APHHS1005_RED 1029.81,2941.18 r180 top value=Red
LED4 "APHHS1005SURCK" APHHS1005_RED 2085.81,3051.18 r180 top value=Red
LED5 "APHHS1005CGCK" APHHS1005_GREEN 1791.81,2388.46 r90 top value=Green
LED6 "APHHS1005SURCK" APHHS1005_Red 2927.72,3056.18 r0 top value=Red
Logo1 "CE Mark" CE_MARK_5MM 1567.81,2896.18 r180 bottom
Logo2 "Texas Instruments" TI_Stacked_Overlay_Small 397.81,2252.18 r90 bottom
Logo3 "FCC disclaimer" FCC_DISCLAIMER 5595.8,4379.73 r180 bottom
Logo4 "WEEE logo" WEEE_Minimum 1868.81,2855.18 r180 bottom
R1 "CRCW04020000Z0ED" 0402 821.04,2960.32 r90 bottom value=0
R2 "CRCW04020000Z0ED" 0402 776.23,2960.32 r90 bottom value=0
R3 "CRCW04020000Z0ED" 0402 664.81,2960.32 r270 bottom value=0
R4 "CRCW04020000Z0ED" 0402 715.05,2960.32 r270 bottom value=0
R5 "CRCW04020000Z0ED" 0402 571.63,2976.48 r180 bottom value=0
R6 "CRCW04020000Z0ED" 0402 571.34,2928.08 r180 bottom value=0
R7 "CRCW04020000Z0ED" 0402 1091.46,2091.18 r270 top value=0
R8 "CRCW04020000Z0ED" 0402 895.46,2091.18 r90 top value=0
R9 "CRCW04020000Z0ED" 0402 1042.46,2091.18 r270 top value=0
R10 "CRCW04020000Z0ED" 0402 846.46,2091.18 r90 top value=0
R11 "CRCW04021K50JNED" 0402 2133.19,2600.18 r180 bottom value=1.5k
R12 "CRCW04021K50JNED" 0402 2116.81,2464.18 r180 bottom value=1.5k
R13 "CRCW04021K50JNED" 0402 2730.81,2455.18 r0 bottom value=1.5k
R14 "CRCW04021K50JNED" 0402 2710.81,2603.18 r0 bottom value=1.5k
R15 "CRCW04021K50JNED" 0402 1292.81,2940.18 r270 bottom value=1.5k
R16 "CRCW04021K50JNED" 0402 1244.81,2940.18 r270 bottom value=1.5k
R17 "CRCW04021K50JNED" 0402 1196.81,2940.18 r270 bottom value=1.5k
R18 "CRCW04021K50JNED" 0402 1148.46,2940.18 r270 bottom value=1.5k
R19 "CRCW0402100RJNED" 0402 1357.81,2247.56 r90 bottom value=100
R20 "CRCW04021K50JNED" 0402 2723.19,2800.18 r180 bottom value=1.5k
R21 "RC0402FR-07470RL" 0402 641.31,2124.63 r180 bottom value=470
R22 "RC0402FR-07470RL" 0402 641.31,2171.68 r180 bottom value=470
R23 "CRCW04021K50JNED" 0402 2615.09,2926.37 r90 bottom value=1.5k
R24 "CRCW04021K50JNED" 0402 2234.88,2796.37 r90 bottom value=1.5k
R25 "CRCW040210K0JNED" 0402 1335.62,2652.31 r270 top value=10k
R26 "CRCW04024K87FKED" 0402 1100.46,2940.18 r270 bottom value=4.87k
R27 "CRCW04021K50JNED" 0402 2146.81,2172.18 r270 top value=1.5k
R28 "CRG0402F4K7" 0402 2750.81,2405.18 r0 bottom value=4.70k
R29 "CRCW04021K50JNED" 0402 2142.81,2879.18 r180 top value=1.5k
R30 "CRCW04020000Z0ED" 0402 662.19,3277.18 r180 bottom value=0
R31 "CRCW04020000Z0ED" 0402 484.19,3219.18 r180 bottom value=0
R32 "CRCW0402680RJNED" 0402 2829.1,3056.18 r180 top value=680
R37 "CRCW040251R0JNED" 0402 1324.81,2768.06 r90 top value=51
R38 "CRCW04020000Z0ED" 0402 1979.43,2485.18 r0 top value=0
R39 "RC0402FR-073KL" 0402 1022.23,2895.12 r180 top value=3.00k
R40 "ERJ-2RKF1004X" 0402 1674.81,2477.56 r90 top value=1.00Meg
R41 "CRCW0402680RJNED" 0402 2078.81,3007.18 r180 top value=680
R42 "CRCW0603200RFKEA" 0603 1495.38,2254.99 r90 bottom value=200
R43 "CRCW0603200RFKEA" 0603 1621.84,2254.99 r90 bottom value=200
R44 "CRCW0603200RFKEA" 0603 1753.19,2254.99 r90 bottom value=200
R45 "CRCW0603200RFKEA" 0603 1881.54,2254.99 r90 bottom value=200
R46 "CRCW0402909KFKED" 0402 1476.35,2569.66 r0 bottom value=909k
R47 "CRG0402F4K7" 0402 1476.81,2524.18 r180 bottom value=4.70k
R48 "CRCW04020000Z0ED" 0402 1603.14,2374.18 r180 bottom value=0
R49 "CRCW0402200KFKED" 0402 1476.81,2618.18 r0 bottom value=200k
R50 "CRCW04021K50JNED" 0402 1825.68,2524.18 r0 bottom value=1.5k
R51 "CRCW04021K50JNED" 0402 1825.68,2471.18 r0 bottom value=1.5k
R52 "CRCW04021K50JNED" 0402 1747.81,2395.56 r90 top value=1.5k
R53 "CRCW04020000Z0ED" 0402 1216.81,3035.18 r180 top value=0
R54 "CRG0402F4K7" 0402 1217.81,2988.18 r0 top value=4.70k
S1 "CAS-120TA" SW_CAS-120TA 2786.08,2707.28 r0 top
S2 "218-2LPST" SW_218-2LP 2774.81,2266.18 r270 top
TP1 "TP_SM_1MM" TP_SM_1MM 910.75,3017.82 r90 bottom
TP2 "TP_SM_1MM" TP_SM_1MM 1884.81,2487.18 r90 top
TP3 "CMP-0078143-4" TESTPOINT 1745.81,2631.18 r90 top
TP4 "CMP-0078143-4" TESTPOINT 1917.81,3039.18 r90 top
TP5 "CMP-0078143-4" TESTPOINT 2023.81,2913.18 r90 top
TP6 "TP_SM_1MM" TP_SM_1MM 1997.81,2811.18 r90 top
TP7 "TP_SM_1MM" TP_SM_1MM 1652.23,2434.63 r90 bottom
U1 "TPD4E05U06DQAR" DQA0010A#1 601.87,3109.19 r0 bottom
U2 "TPD4E05U06DQAR" DQA0010A#1 461.25,2983.19 r0 bottom
U3 "TPD1E10B06DPYR" DPY0002A#1 357.99,2951 r270 bottom
U4 "TPD4E05U06DQAR" DQA0010A#2 929.81,2194.18 r270 top
U5 "TPD6E05U06RVZR" RVZ0014A 717.12,2738.79 r90 top
U6 "ISO1644DWR" DW0016B-MFG 2425.81,2529.18 r0 bottom
U7 "ISO1644DWR" DW0016B-MFG 2426.81,2813.18 r0 top
U8 "SN74LVC2G126DCUR" DCU0008A_N 623.82,3211.65 r180 bottom
U9 "MSP432E401YTPDT" PDT0128A 946.18,2538.03 r0 bottom locked
U12 "ISO7741DWR" DW0016B_HV 2426.87,2280.18 r180 top
U13 "TPD4E05U06DQAR" DQA0010A#1 2828.37,2741.5 r0 bottom
U14 "TPD4E05U06DQAR" DQA0010A#1 2825.37,2527.81 r180 bottom
U17 "TPD1E10B06DPYR" DPY0002A#2 2841.81,2993.18 r270 top
U18 "TPD4E05U06DQAR" DQA0010A#1 2831.25,2229.87 r0 bottom
U19 "TLV70333DBVR" DBV0005A-MFG 1850.41,2764 r90 top
U20 "LM4120IM5-4.1/NOPB" DBV0005A_N 2056.81,2665.18 r180 top
U21 "DAC128S085CIMT/NOPB" PW0016A-MFG 1984.87,2305.57 r270 top
U22 "TPD1E10B06DPYR" DPY0002A#2 1621.81,2611.18 r0 top
U23 "TUSB320LIRWBR" RWB0012A 1579.86,2490.99 r0 bottom
U24 "TPD4E05U06DQAR" DQA0010A#2 1500.22,2535.03 r270 top
U25 "SN74AHC1G02DRLR" DRL0005A 1713.81,2496.39 r180 bottom
U26 "SN74LVC1G04DCKR" DCK0005A_N 1241.43,2898.37 r270 top
Y1 "830064296" FP-830064296_SMT4_3MM4_2MM7-MFG 1394.8,2399.49 r270 bottom
ZZ1 "This Assembly Note is for PCB labels only" ASSEMBLYNOTELABEL 4897,5513.23 r0 top
ZZ2 "These assemblies are ESD sensitive, ESD precautions shall be observed." ASSEMBLYNOTE 4897,5636.23 r0 top
ZZ3 "These assemblies must be clean and free from flux and all contaminants. Use of no clean flux is not acceptable." ASSEMBLYNOTE 4897,5736.23 r0 top
ZZ4 "These assemblies must comply with workmanship standards IPC-A-610 Class 2, unless otherwise specified." ASSEMBLYNOTE 4897,5847.23 r0 top

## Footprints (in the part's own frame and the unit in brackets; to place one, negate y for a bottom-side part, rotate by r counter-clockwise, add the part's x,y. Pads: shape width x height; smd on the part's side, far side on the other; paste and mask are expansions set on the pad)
0402 [mm]
  rect 0.8x0.6 smd: 1(-0.6,0) 2(0.6,0)
  silkscreen extent -1.22,-0.52 1.22,0.52, body extent -0.55,-0.3 0.55,0.3, height 0.6
0603 [mm]
  rect 1x0.95 smd: 1(-0.8,0) 2(0.8,0)
  silkscreen extent -1.52,-0.69 1.52,0.69, body extent -0.87,-0.47 0.87,0.47, height 1
APHHS1005_GREEN [mm]
  rrect20% 0.7x0.5 smd: 1(-0.45,0) 2(0.45,0)
  silkscreen extent -0.8,-0.64 1.2,0.66, body extent -0.5,-0.25 0.5,0.25, height 0.5
APHHS1005_RED [mm]
  rrect20% 0.7x0.5 smd: 1(-0.45,0) 2(0.45,0)
  silkscreen extent -0.8,-0.65 1.21,0.65, body extent -0.5,-0.25 0.5,0.25, height 0.5
APHHS1005_Red [mm] "SMD, 2-Leads, Body 1x0.5mm"
  rrect20% 0.7x0.5 smd: 1(-0.45,0) 2(0.45,0)
  silkscreen extent -0.8,-0.65 1.2,0.65, body extent -0.5,-0.25 0.5,0.25, height 0.5
ASSEMBLYNOTE [mil] "Assembly Note"
ASSEMBLYNOTELABEL [mil]
BRAKE_WAY_HOLES1X3 [mil]
  round 27 hole 32 unplated mask+5.5: ""(-50,29.37) ""(0,29.37) ""(50,29.37)
CE_MARK_5MM [mil]
  silkscreen extent -138,-99 138,99
DBV0005A-MFG [mm]
  rrect17% 1.1x0.6 smd paste+0 mask+0: 1(-1.3,0.95) 2(-1.3,0) 3(-1.3,-0.95) 4(1.3,-0.95) 5(1.3,0.95)
  silkscreen extent -2.57,-1.53 0.87,1.53, body extent -1.95,-1.78 1.95,1.78, height 0.25
DBV0005A_N [mm]
  rrect17% 1x0.6 smd: 1(-1.375,0.95) 2(-1.375,0) 3(-1.375,-0.95) 4(1.375,-0.95) 5(1.375,0.95)
  silkscreen extent -1.63,-1.55 0.38,1.55, body extent -1.42,-1.46 1.42,1.46, height 1.09
DCK0005A_N [mm]
  rrect25% 0.85x0.4 smd: 1(-1.125,0.65) 2(-1.125,0) 3(-1.125,-0.65) 4(1.125,-0.65) 5(1.125,0.65)
  silkscreen extent -1.48,-1.02 0.55,1.1, body extent -1.14,-1 1.14,1, height 0.95
DCU0008A_N [mm] "TSSOP, 8-Leads, Body 2x2.3mm, Pitch 0.5mm, IPC Medium Density"
  oval 0.8x0.3 smd: 1(-1.6,0.75) 2(-1.6,0.25) 3(-1.6,-0.25) 4(-1.6,-0.75) 5(1.6,-0.75) 6(1.6,-0.25) 7(1.6,0.25) 8(1.6,0.75)
  silkscreen extent -1.05,-1.05 0.38,1.05, body extent -1.56,-1 1.56,1, height 0.9
DPY0002A#1 [mm]
  rrect57% 0.35x0.6 smd paste-0.5 mask-0.05: 1(-0.325,0) 2(0.325,0)
  rrect50% 0.3x0.5 on Bottom Paste: 1S(-0.35,0) 2S(0.35,0)
  silkscreen extent -0.85,-0.03 -0.8,0.02, body extent -0.5,-0.3 0.5,0.3, height 0.45
DPY0002A#2 [mm]
  rrect57% 0.35x0.6 smd paste-0.5 mask-0.05: 1(-0.325,0) 2(0.325,0)
  rrect50% 0.3x0.5 on Top Paste: 1S(-0.35,0) 2S(0.35,0)
  silkscreen extent -0.85,-0.02 -0.8,0.03, body extent -0.5,-0.3 0.5,0.3, height 0.45
DQA0010A#1 [mm]
  rrect50% 0.565x0.2 smd: 1(-0.417,1) 2(-0.417,0.5) 4(-0.417,-0.5) 5(-0.417,-1) 6(0.417,-1) 7(0.417,-0.5) 9(0.417,0.5) 10(0.417,1)
  rrect50% 0.565x0.36 on Bottom Paste: 3(-0.417,0) 8(0.417,0)
  rrect25% 0.565x0.4 smd paste-0.2: 3(-0.417,0) 8(0.417,0)
  silkscreen extent -0.67,-1.45 0.55,1.45, body extent -0.55,-1.3 0.55,1.3, height 0.56
DQA0010A#2 [mm]
  rrect50% 0.565x0.2 smd: 1(-0.417,1) 2(-0.417,0.5) 4(-0.417,-0.5) 5(-0.417,-1) 6(0.417,-1) 7(0.417,-0.5) 9(0.417,0.5) 10(0.417,1)
  rrect50% 0.565x0.36 on Top Paste: 3(-0.417,0) 8(0.417,0)
  rrect25% 0.565x0.4 smd paste-0.2: 3(-0.417,0) 8(0.417,0)
  silkscreen extent -0.67,-1.45 0.55,1.45, body extent -0.55,-1.3 0.55,1.3, height 0.56
DRL0005A [mm]
  rrect33% 0.67x0.3 smd: 1(-0.74,0.5) 2(-0.74,0) 3(-0.74,-0.5) 4(0.74,-0.5) 5(0.74,0.5)
  silkscreen extent -0.9,-0.95 0.5,0.95, body extent -0.85,-0.85 0.85,0.85, height 0.62
DW0016B-MFG [mm]
  rrect17% 1.65x0.6 smd paste+0 mask+0: 1(-4.875,4.445) 2(-4.875,3.175) 3(-4.875,1.905) 4(-4.875,0.635) 5(-4.875,-0.635) 6(-4.875,-1.905) 7(-4.875,-3.175) 8(-4.875,-4.445) 9(4.875,-4.445) 10(4.875,-3.175) 11(4.875,-1.905) 12(4.875,-0.635) 13(4.875,0.635) 14(4.875,1.905) 15(4.875,3.175) 16(4.875,4.445)
  silkscreen extent -3.5,-5.25 3.5,5.97, body extent -5.15,-5.15 5.15,5.15, height 2.65
DW0016B_HV [mm] "SOIC-16, HV/isolation option"
  rrect17% 1.65x0.6 smd: 1(-4.875,4.445) 2(-4.875,3.175) 3(-4.875,1.905) 4(-4.875,0.635) 5(-4.875,-0.635) 6(-4.875,-1.905) 7(-4.875,-3.175) 8(-4.875,-4.445) 9(4.875,-4.445) 10(4.875,-3.175) 11(4.875,-1.905) 12(4.875,-0.635) 13(4.875,0.635) 14(4.875,1.905) 15(4.875,3.175) 16(4.875,4.445)
  body extent -5.17,-5.15 5.17,5.15, height 2.59
FCC_DISCLAIMER [mil]
FIDUCIAL10-20 [mm]
  round 1 smd mask+0.5: 1(0,0)
  Top Layer keep-out circle w1.178: c0,0 r0.5
FP-830064296_SMT4_3MM4_2MM7-MFG [mm]
  rrect9% 1.4x1.15 smd paste+0 mask+0: 1(-1.1,-0.8) 2(1.1,-0.8) 3(1.1,0.8) 4(-1.1,0.8)
  silkscreen extent -2.17,-2.05 2.17,1.35, body extent -1.7,-1.35 1.7,1.35, height 0.8
FP-GRM155C61E475ME15D_0402-MFG [mm]
  rrect22% 0.45x0.6 smd paste+0 mask+0: 1(-0.475,0) 2(0.475,0)
  silkscreen extent -0.6,-0.64 0.6,0.65, body extent -0.5,-0.25 0.5,0.25, height 0.7
FP-GRM155R61A106ME18D_0402-MFG [mm]
  rrect22% 0.45x0.6 smd paste+0 mask+0: 1(-0.475,0) 2(0.475,0)
  silkscreen extent -0.6,-0.64 0.6,0.65, body extent -0.8,-0.45 0.8,0.45, height 0.25
FP-GRM1555C1E103JE01D_0402-MFG [mm]
  rrect22% 0.45x0.6 smd paste+0 mask+0: 1(-0.475,0) 2(0.475,0)
  silkscreen extent -0.58,-0.73 0.58,0.72, body extent -0.5,-0.25 0.5,0.25, height 0.65
FP-GRT1555C1H120JA02D_0402-MFG [mm]
  rrect25% 0.4x0.5 smd paste+0 mask+0: 1(-0.4,0) 2(0.4,0)
  silkscreen extent -0.5,-0.67 0.5,0.67, body extent -0.5,-0.25 0.5,0.25, height 0.55
FP-SSW-108-02-G-D-RA-008_CONN_RCPT15-MFG [mm]
  rrect6% 1.59x1.59 hole 1.04 paste-1000 mask+0: 1(-8.89,-5.779)
  round 1.59 hole 1.04 paste-1000 mask+0: 2(-8.89,-8.319) 3(-6.35,-5.779) 4(-6.35,-8.319) 5(-3.81,-5.779) 6(-3.81,-8.319) 7(-1.27,-5.779) 8(-1.27,-8.319) 9(1.27,-5.779) 10(1.27,-8.319) 11(3.81,-5.779) 12(3.81,-8.319) 13(6.35,-5.779) 14(6.35,-8.319) 15(8.89,-5.779) 16(8.89,-8.319)
  silkscreen extent -10.54,-5.9 10.54,4.39, body extent -10.64,-9.21 10.64,4.48, height 0.25
LABEL_650X200 [mil]
  round 1 on Mech14: 0(0,0)
  silkscreen extent -325,84 325,84
PDT0128A [mm]
  oval 1.4x0.2 smd: 1(-7.7,6.2) 2(-7.7,5.8) 3(-7.7,5.4) 4(-7.7,5) 5(-7.7,4.6) 6(-7.7,4.2) 7(-7.7,3.8) 8(-7.7,3.4) 9(-7.7,3) 10(-7.7,2.6) 11(-7.7,2.2) 12(-7.7,1.8) 13(-7.7,1.4) 14(-7.7,1) 15(-7.7,0.6) 16(-7.7,0.2) 17(-7.7,-0.2) 18(-7.7,-0.6) 19(-7.7,-1) 20(-7.7,-1.4) 21(-7.7,-1.8) 22(-7.7,-2.2) 23(-7.7,-2.6) 24(-7.7,-3) 25(-7.7,-3.4) 26(-7.7,-3.8) 27(-7.7,-4.2) 28(-7.7,-4.6) 29(-7.7,-5) 30(-7.7,-5.4) 31(-7.7,-5.8) 32(-7.7,-6.2) 65(7.7,-6.2) 66(7.7,-5.8) 67(7.7,-5.4) 68(7.7,-5) 69(7.7,-4.6) 70(7.7,-4.2) 71(7.7,-3.8) 72(7.7,-3.4) 73(7.7,-3) 74(7.7,-2.6) 75(7.7,-2.2) 76(7.7,-1.8) 77(7.7,-1.4) 78(7.7,-1) 79(7.7,-0.6) 80(7.7,-0.2) 81(7.7,0.2) 82(7.7,0.6) 83(7.7,1) 84(7.7,1.4) 85(7.7,1.8) 86(7.7,2.2) 87(7.7,2.6) 88(7.7,3) 89(7.7,3.4) 90(7.7,3.8) 91(7.7,4.2) 92(7.7,4.6) 93(7.7,5) 94(7.7,5.4) 95(7.7,5.8) 96(7.7,6.2)
  oval 0.2x1.4 smd: 33(-6.2,-7.7) 34(-5.8,-7.7) 35(-5.4,-7.7) 36(-5,-7.7) 37(-4.6,-7.7) 38(-4.2,-7.7) 39(-3.8,-7.7) 40(-3.4,-7.7) 41(-3,-7.7) 42(-2.6,-7.7) 43(-2.2,-7.7) 44(-1.8,-7.7) 45(-1.4,-7.7) 46(-1,-7.7) 47(-0.6,-7.7) 48(-0.2,-7.7) 49(0.2,-7.7) 50(0.6,-7.7) 51(1,-7.7) 52(1.4,-7.7) 53(1.8,-7.7) 54(2.2,-7.7) 55(2.6,-7.7) 56(3,-7.7) 57(3.4,-7.7) 58(3.8,-7.7) 59(4.2,-7.7) 60(4.6,-7.7) 61(5,-7.7) 62(5.4,-7.7) 63(5.8,-7.7) 64(6.2,-7.7) 97(6.2,7.7) 98(5.8,7.7) 99(5.4,7.7) 100(5,7.7) 101(4.6,7.7) 102(4.2,7.7) 103(3.8,7.7) 104(3.4,7.7) 105(3,7.7) 106(2.6,7.7) 107(2.2,7.7) 108(1.8,7.7) 109(1.4,7.7) 110(1,7.7) 111(0.6,7.7) 112(0.2,7.7) 113(-0.2,7.7) 114(-0.6,7.7) 115(-1,7.7) 116(-1.4,7.7) 117(-1.8,7.7) 118(-2.2,7.7) 119(-2.6,7.7) 120(-3,7.7) 121(-3.4,7.7) 122(-3.8,7.7) 123(-4.2,7.7) 124(-4.6,7.7) 125(-5,7.7) 126(-5.4,7.7) 127(-5.8,7.7) 128(-6.2,7.7)
  silkscreen extent -7.7,-6.3 6.3,6.99, body extent -8,-8 8,8, height 1.07
PW0016A-MFG [mm]
  rrect22% 1.5x0.45 smd paste+0 mask+0: 1(-2.9,2.275) 2(-2.9,1.625) 3(-2.9,0.975) 4(-2.9,0.325) 5(-2.9,-0.325) 6(-2.9,-0.975) 7(-2.9,-1.625) 8(-2.9,-2.275) 9(2.9,-2.275) 10(2.9,-1.625) 11(2.9,-0.975) 12(2.9,-0.325) 13(2.9,0.325) 14(2.9,0.975) 15(2.9,1.625) 16(2.9,2.275)
  silkscreen extent -3.2,-2.55 1.78,3.2, body extent -3.75,-2.8 3.75,2.8, height 0.25
RVZ0014A [mm] "SON, 14-Leads, Body 3.5x1.35mm, Pitch 0.5mm"
  rrect50% 0.5x0.2 smd: 1(-0.625,1.5) 2(-0.625,1) 3(-0.625,0.5) 4(-0.625,0) 5(-0.625,-0.5) 6(-0.625,-1) 7(-0.625,-1.5) 8(0.625,-1.5) 9(0.625,-1) 10(0.625,-0.5) 11(0.625,0) 12(0.625,0.5) 13(0.625,1) 14(0.625,1.5)
  silkscreen extent -1.18,-2.05 1.18,2.05, body extent -0.72,-1.8 0.72,1.8, height 0.55
RWB0012A [mm]
  rrect57% 0.7x0.2 smd paste-0.1: 1(-0.65,0.2) 2(-0.65,-0.2) 7(0.65,-0.2) 8(0.65,0.2)
  rrect57% 0.2x0.5 smd: 3(-0.6,-0.75) 4(-0.2,-0.75) 5(0.2,-0.75) 6(0.6,-0.75) 9(0.6,0.75) 10(0.2,0.75) 11(-0.2,0.75) 12(-0.6,0.75)
  silkscreen extent -0.92,-0.91 0.92,0.91, body extent -0.8,-0.8 0.8,0.8, height 0.4
SAMTEC_QTH-060-01-L-D-A [mm]
  rect 0.305x1.45 smd: 1(-17.25,3.086) 2(-17.25,-3.086) 3(-16.75,3.086) 4(-16.75,-3.086) 5(-16.25,3.086) 6(-16.25,-3.086) 7(-15.75,3.086) 8(-15.75,-3.086) 9(-15.25,3.086) 10(-15.25,-3.086) 11(-14.75,3.086) 12(-14.75,-3.086) 13(-14.25,3.086) 14(-14.25,-3.086) 15(-13.75,3.086) 16(-13.75,-3.086) 17(-13.25,3.086) 18(-13.25,-3.086) 19(-12.75,3.086) 20(-12.75,-3.086) 21(-12.25,3.086) 22(-12.25,-3.086) 23(-11.75,3.086) 24(-11.75,-3.086) 25(-11.25,3.086) 26(-11.25,-3.086) 27(-10.75,3.086) 28(-10.75,-3.086) 29(-10.25,3.086) 30(-10.25,-3.086) 31(-9.75,3.086) 32(-9.75,-3.086) 33(-9.25,3.086) 34(-9.25,-3.086) 35(-8.75,3.086) 36(-8.75,-3.086) 37(-8.25,3.086) 38(-8.25,-3.086) 39(-7.75,3.086) 40(-7.75,-3.086) 41(-7.25,3.086) 42(-7.25,-3.086) 43(-6.75,3.086) 44(-6.75,-3.086) 45(-6.25,3.086) 46(-6.25,-3.086) 47(-5.75,3.086) 48(-5.75,-3.086) 49(-5.25,3.086) 50(-5.25,-3.086) 51(-4.75,3.086) 52(-4.75,-3.086) 53(-4.25,3.086) 54(-4.25,-3.086) 55(-3.75,3.086) 56(-3.75,-3.086) 57(-3.25,3.086) 58(-3.25,-3.086) 59(-2.75,3.086) 60(-2.75,-3.086) 61(2.75,3.086) 62(2.75,-3.086) 63(3.25,3.086) 64(3.25,-3.086) 65(3.75,3.086) 66(3.75,-3.086) 67(4.25,3.086) 68(4.25,-3.086) 69(4.75,3.086) 70(4.75,-3.086) 71(5.25,3.086) 72(5.25,-3.086) 73(5.75,3.086) 74(5.75,-3.086) 75(6.25,3.086) 76(6.25,-3.086) 77(6.75,3.086) 78(6.75,-3.086) 79(7.25,3.086) 80(7.25,-3.086) 81(7.75,3.086) 82(7.75,-3.086) 83(8.25,3.086) 84(8.25,-3.086) 85(8.75,3.086) 86(8.75,-3.086) 87(9.25,3.086) 88(9.25,-3.086) 89(9.75,3.086) 90(9.75,-3.086) 91(10.25,3.086) 92(10.25,-3.086) 93(10.75,3.086) 94(10.75,-3.086) 95(11.25,3.086) 96(11.25,-3.086) 97(11.75,3.086) 98(11.75,-3.086) 99(12.25,3.086) 100(12.25,-3.086) 101(12.75,3.086) 102(12.75,-3.086) 103(13.25,3.086) 104(13.25,-3.086) 105(13.75,3.086) 106(13.75,-3.086) 107(14.25,3.086) 108(14.25,-3.086) 109(14.75,3.086) 110(14.75,-3.086) 111(15.25,3.086) 112(15.25,-3.086) 113(15.75,3.086) 114(15.75,-3.086) 115(16.25,3.086) 116(16.25,-3.086) 117(16.75,3.086) 118(16.75,-3.086) 119(17.25,3.086) 120(17.25,-3.086)
  rect 2.54x0.64 smd: A1(-18.44,0) A4(-1.55,0) A5(1.56,0) A8(18.45,0)
  rect 4.7x0.64 smd: A2(-13.17,0) A3(-6.82,0) A6(6.83,0) A7(13.18,0)
  round 1.15 hole 1.15 unplated mask+0: MH1(-19.24,2.03) MH2(19.24,2.03)
  silkscreen extent -20,-2.99 20,2.99, body extent -20.07,-3.56 19.94,3.56, height 4.32
Samtec_TSM-106-01-x-DV [mm] "Header, 2.54mm, 6x2, SMT"
  rect 3.68x1.27 smd: 1(-2.475,6.35) 2(2.475,6.35) 3(-2.475,3.81) 4(2.475,3.81) 5(-2.475,1.27) 6(2.475,1.27) 7(-2.475,-1.27) 8(2.475,-1.27) 9(-2.475,-3.81) 10(2.475,-3.81) 11(-2.475,-6.35) 12(2.475,-6.35)
  silkscreen extent -1.65,-7.62 1.65,7.76, body extent -3.85,-7.62 3.85,7.62, height 9.65
SW_218-2LP [mm]
  rect 1.27x0.76 smd: 1(-3.81,0.635) 2(-3.81,-0.635) 3(3.81,-0.635) 4(3.81,0.635)
  silkscreen extent -2.9,-1.86 2.9,2.07, body extent -4.22,-1.86 4.22,1.85, height 2.62
SW_CAS-120TA [mm]
  rect 1.6x1 smd: 1(-1.15,1.75) 2(1.15,0) 3(-1.15,-1.75)
  silkscreen extent -2,-2.85 1.4,2.93, body extent -1.4,-2.85 1.4,2.85, height 2.51
TESTPOINT [mil]
  round 80 hole 37.99: 1(0,0)
  silkscreen extent -53,-54 53,54
TI_Stacked_Overlay_Small [mil]
  silkscreen extent -418,-98 418,98
TP_SM_1MM [mm]
  round 1 smd paste-0.5: 1(0,0)
TSW-105-08-G-S-RA [mm] "Samtec Right Angle Header"
  rrect6% 1.65x1.65 hole 1: 1(-5.08,0)
  round 1.65 hole 1: 2(-2.54,0) 3(0,0) 4(2.54,0) 5(5.08,0)
  silkscreen extent -6.85,-9.65 6.35,1.39, body extent -6.35,-9.91 6.35,0.32, height 3.05
WEEE_Minimum [mil] "WEEElie bin"
  silkscreen extent -95,-172 99,104
WURTH_632_723_300_011 [mm] "Connector, Receptacle, USB Type C, R/A"
  rect 0.3x1.2 smd: A1(-2.75,10.58) A2(-2.25,10.58) A3(-1.75,10.58) A4(-1.25,10.58) A5(-0.75,10.58) A6(-0.25,10.58) A7(0.25,10.58) A8(0.75,10.58) A9(1.25,10.58) A10(1.75,10.58) A11(2.25,10.58) A12(2.75,10.58)
  round 0.55 hole 0.4: B1(2.8,9.32) B2(2.4,8.62) B3(1.6,8.62) B4(1.2,9.32) B5(0.8,8.62) B6(0.4,9.32) B7(-0.4,9.32) B8(-0.8,8.62) B9(-1.2,9.32) B10(-1.6,8.62) B11(-2.4,8.62) B12(-2.8,9.32) M1(2,9.32) M2(-2,9.32)
  rrect100% 1x1.6 hole 0.6 slot 1.2 at 90 deg: S1(-4.27,8.18) S2(-4.27,3.45) S3(4.27,3.45) S4(4.27,8.18)
  silkscreen extent -4.37,0.15 4.37,10.36, body extent -4.37,-0.96 4.37,10.83, height 3.07

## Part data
C1 C2 C3 C4: library part CMP-0006456-2, "CAP, CERM, 330 pF, 50 V, +/- 5%, C0G/NP0, 0402", Cap_Case=0402, Manufacturer=MuRata, Supplier Part Number 1=490-1295-1-ND, TempCo=C0G/NP0, Tolerance_%=5%, Value1=Unknown, Value2=50V, ValueDisplayed=330pF
C5 C9 C10 C14 C15 C17 C18 C48 C53 C55 C56 C57 C58 C59 C64 C65: library part CMP-0006659-2, "CAP, CERM, 0.1 uF, 25 V, +/- 10%, X7R, 0402", Cap_Case=0402, Manufacturer=MuRata, Supplier Part Number 1=490-10698-1-ND, TempCo=X7R, Tolerance_%=10%, Value1=Unknown, Value2=25V, ValueDisplayed=0.1uF
C11 C21 C22 C23 C24 C25 C26 C27 C30 C31 C32 C33 C34 C35 C36 C44 C46: library part CMP-0035343-1, "Chip Multilayer Ceramic Capacitors for General Purpose, 0402, 10000pF, C0G, 30ppm/°C, 5%, 25V", Manufacturer=Murata, Operating Temperature Range="-55°C to +125°C", TempCo=30ppm/°C, Temperature Characteristic=C0G, Tolerance_%=5%, ValueDisplayed=10000pF
C12 C13 C51 C52 C54: library part CMP-0120206-1, "4.7 µF ±20% 25V Ceramic Capacitor X5S 0402 (1005 Metric)", Manufacturer=Murata, Operating Temperature Range="-55°C to +85°C", TempCo=22%, Temperature Characteristic=X5S, Tolerance_%=20%, ValueDisplayed=4.7uF
C16: library part CMP-0120207-1, "10 µF ±20% 10V Ceramic Capacitor X5R 0402 (1005 Metric)", Manufacturer=Murata, Operating Temperature Range="-55°C to +85°C", TempCo=15%, Temperature Characteristic=X5R, Tolerance_%=20%, ValueDisplayed=10uF
C19 C20: library part CMP-0120209-1, "Multi-Layer Ceramic Capacitor 12pF 50V C0G ±5% 0402 Paper T/R", Manufacturer=Murata, Operating Temperature Range="-55°C to +125°C", TempCo=30ppm/°C, Temperature Characteristic=C0G, Tolerance_%=5%, ValueDisplayed=12pF
C37 C38 C39 C40 C43 C47: library part CMP-0086061-1, "CAP, CERM, 1 µF, 25 V,+/- 10%, X5R, 0402", Cap_Case=0402, Manufacturer=MuRata, TempCo=X5R, Tolerance_%=10%, Value2=25V, ValueDisplayed=1µF
C45: library part CMP-0081010-1, "CAP, CERM, 2.2 µF, 25 V,+/- 20%, X5R, 0402", Cap_Case=0402, Manufacturer=MuRata, Supplier Part Number 1=490-10457-1-ND, TempCo=X5R, Tolerance_%=20%, Value2=25V, ValueDisplayed=2.2µF
C49: library part CMP-0007336-5, "CAP, CERM, 10 uF, 16 V, +/- 20%, X5R, 0603", Cap_Case=0603, Manufacturer=MuRata, Supplier Part Number 1=GRM188R61C106MAALD-ND, TempCo=X5R, Tolerance_%=20%, Value1=Unknown, Value2=16V, ValueDisplayed=10uF
C50: library part CMP-0006634-2, "CAP, CERM, 0.047 uF, 10 V, +/- 10%, X7R, 0402", Cap_Case=0402, Manufacturer=MuRata, Supplier Part Number 1=490-1316-1-ND, TempCo=X7R, Tolerance_%=10%, Value1=Unknown, Value2=10V, ValueDisplayed=0.047uF
C60 C61 C62 C63: library part CMP-0007174-4, "CAP, CERM, 0.01 uF, 50 V, +/- 5%, C0G/NP0, 0603", Cap_Case=0603, Manufacturer=MuRata, Supplier Part Number 1=490-9666-1-ND, TempCo=C0G/NP0, Tolerance_%=5%, Value1=Unknown, Value2=50V, ValueDisplayed=0.01uF
FID1 FID2 FID3 FID5 FID6 FID7 FID8 FID9 FID10 FID11 FID12 FID13 FID14 FID15: library part CMP-0077181-1, "Fiducial mark.  There is nothing to buy or mount.", Manufacturer=N/A
J1: library part CMP-0056023-2, "Socket, 0.5MM, 60x2, Gold, SMT", Manufacturer=Samtec, Supplier Part Number 1=SAM8189-ND
J2: library part CMP-0075594-2, "Header, 2.54mm, 6x2, Gold, SMT", Color=Black, Current_A=4.9A, Manufacturer=Samtec, Supplier Part Number 1=TSM-106-01-L-DV-ND, Voltage_V=475V
J3: library part CMP-0122457-1, "Conn Socket Strip SKT 16 POS 2.54mm Solder RA Thru-Hole", Current_A=4.7A, Digikey Part Number=SSW-108-02-G-D-RA-008-ND, Manufacturer=Samtec, Operating Temperature Range="-55°C to +125°C", Voltage_V=655V
J5: library part CMP-0080891-1, "Connector, Receptacle, USB Type C, R/A", Color=Black, Current_A=3A, Manufacturer="Wurth Elektronik", Supplier Part Number 1=732-9618-1-ND, Voltage_V=5V
J6: library part CMP-0055979-1, "Header, 100mil, 5x1, Gold, R/A, TH", Color=Black, Current_A=6.3A, Manufacturer=Samtec, Supplier Part Number 1=SAM1039-05-ND, Voltage_V=550V
L1: library part CMP-0003333-1, "Ferrite Bead, 120 ohm @ 100 MHz, 0.3 A, 0402", Manufacturer=MuRata, Supplier Part Number 1=490-5192-1-ND, Value1="0.3 ohm", Value2=0.3A, ValueDisplayed="120 ohm"
L2 L3: library part CMP-0003309-1, "Ferrite Bead, 10 ohm @ 100 MHz, 1 A, 0402", Manufacturer=MuRata, Supplier Part Number 1=490-5176-1-ND, Value1="0.025 ohm", Value2=1A, ValueDisplayed="10 ohm"
LBL1: library part CMP-0003625-1, "Thermal Transfer Printable Labels, 0.650\" W x 0.200\" H - 10,000 per roll", Manufacturer=Brady, Supplier Part Number 1=97C5133
LED1 LED2 LED5: library part CMP-0067682-2, "LED, Green, SMD", Color=Green, Manufacturer=Kingbright, Power_TotalModule=75mW, Value1=0.075W, Value2=2.1V
LED3 LED4 LED6: library part CMP-0067681-2, "LED, Red, SMD", Color=Red, Manufacturer=Kingbright, Power_TotalModule=75mW, Value1=0.075W, Value2=1.95V
Logo1: library part CMP-0074844-2, Manufacturer="Texas Instruments"
Logo2: library part CMP-0074838-1, "Texas Instrument Corporate Signature"
Logo3: library part CMP-0074847-1, "FCC_disclaimer"
Logo4: library part CMP-0074769-4, Manufacturer="Texas Instruments"
R1 R2 R3 R4 R5 R6 R7 R8 R9 R10 R30 R31 R38 R48 R53: library part CMP-0026822-3, "RES, 0, 5%, 0.063 W, AEC-Q200 Grade 0, 0402", Manufacturer=Vishay-Dale, Power_W=63mW, Supplier Part Number 1=541-0.0JCT-ND, TempCo="200 ppm/C", Tolerance_%=5%, Value2=0.063W, Value_Code=0000, ValueDisplayed=0
R11 R12 R13 R14 R15 R16 R17 R18 R20 R23 R24 R27 R29 R50 R51 R52: library part CMP-0026856-5, "RES, 1.5 k, 5%, 0.063 W, AEC-Q200 Grade 0, 0402", Manufacturer=Vishay-Dale, Power_W=63mW, Supplier Part Number 1=541-1.5KJCT-ND, TempCo="200 ppm/C", Tolerance_%=5%, Value2=0.063W, Value_Code=1k50, ValueDisplayed=1.5k
R19: library part CMP-0026824-3, "RES, 100, 5%, 0.063 W, AEC-Q200 Grade 0, 0402", Manufacturer=Vishay-Dale, Power_W=63mW, Supplier Part Number 1=541-100JCT-ND, TempCo="200 ppm/C", Tolerance_%=5%, Value2=0.063W, Value_Code=100R, ValueDisplayed=100
R21 R22: library part CMP-0026736-1, "RES, 470, 1%, 0.063 W, 0402", Manufacturer="Yageo America", Power_W=63mW, Supplier Part Number 1=311-470LRCT-ND, TempCo="100 ppm/C", Tolerance_%=1%, Value2=0.063W, Value_Code=470R, ValueDisplayed=470
R25: library part CMP-0026825-5, "RES, 10 k, 5%, 0.063 W, AEC-Q200 Grade 0, 0402", Manufacturer=Vishay-Dale, Power_W=63mW, Supplier Part Number 1=541-10KJCT-ND, TempCo="200 ppm/C", Tolerance_%=5%, Value2=0.063W, Value_Code=10k0, ValueDisplayed=10k
R26: library part CMP-0026413-2, "RES, 4.87 k, 1%, 0.063 W, AEC-Q200 Grade 0, 0402", Manufacturer=Vishay-Dale, Power_W=63mW, Supplier Part Number 1=541-4.87KLCT-ND, TempCo="100 ppm/C", Tolerance_%=1%, Value2=0.063W, Value_Code=4k87, ValueDisplayed=4.87k
R28 R47 R54: library part CMP-0026631-1, "RES, 4.70 k, 1%, 0.063 W, 0402", Manufacturer="TE Connectivity", Power_W=63mW, Supplier Part Number 1=A121542CT-ND, TempCo="100 ppm/C", Tolerance_%=1%, Value2=0.063W, Value_Code=4k70, ValueDisplayed=4.70k
R32 R41: library part CMP-0026962-3, "RES, 680, 5%, 0.063 W, AEC-Q200 Grade 0, 0402", Manufacturer=Vishay-Dale, Power_W=63mW, Supplier Part Number 1=541-680JCT-ND, TempCo="200 ppm/C", Tolerance_%=5%, Value2=0.063W, Value_Code=680R, ValueDisplayed=680
R37: library part CMP-0026946-3, "RES, 51, 5%, 0.063 W, AEC-Q200 Grade 0, 0402", Manufacturer=Vishay-Dale, Power_W=63mW, Supplier Part Number 1=541-51JCT-ND, TempCo="200 ppm/C", Tolerance_%=5%, Value2=0.063W, Value_Code=51R0, ValueDisplayed=51
R39: library part CMP-0026733-1, "RES, 3.00 k, 1%, 0.0625 W, 0402", Manufacturer="Yageo America", Power_W=62.5mW, Supplier Part Number 1=311-3KLRCT-ND, TempCo="100 ppm/C", Tolerance_%=1%, Value2=0.0625W, Value_Code=3k00, ValueDisplayed=3.00k
R40: library part CMP-0026660-1, "RES, 1.00 M, 1%, 0.1 W, 0402", Manufacturer=Panasonic, Power_W=100mW, Supplier Part Number 1=P1.00MLCT-ND, TempCo="100 ppm/C", Tolerance_%=1%, Value2=0.1W, Value_Code=1M00, ValueDisplayed=1.00M
R42 R43 R44 R45: library part CMP-0022201-5, "RES, 200, 1%, 0.1 W, AEC-Q200 Grade 0, 0603", Manufacturer=Vishay-Dale, Power_W=100mW, Supplier Part Number 1=541-200HCT-ND, TempCo="100 ppm/C", Tolerance_%=1%, Value2=0.1W, Value_Code=200R, ValueDisplayed=200
R46: library part CMP-0026603-2, "RES, 909 k, 1%, 0.063 W, AEC-Q200 Grade 0, 0402", Manufacturer=Vishay-Dale, Power_W=63mW, Supplier Part Number 1=541-909KLCT-ND, TempCo="100 ppm/C", Tolerance_%=1%, Value2=0.063W, Value_Code=909k
R49: library part CMP-0026158-2, "RES, 200 k, 1%, 0.063 W, AEC-Q200 Grade 0, 0402", Manufacturer=Vishay-Dale, Power_W=63mW, Supplier Part Number 1=541-200KLCT-ND, TempCo="100 ppm/C", Tolerance_%=1%, Value2=0.063W, Value_Code=200k
S1: library part CMP-0002139-2, "Switch, Slide, SPDT  100mA, SMT", CurrentRating_mA=100A, Manufacturer="Copal Electronics", Supplier Part Number 1=CAS120JCT-ND
S2: library part CMP-0002230-1, "Switch, SPST, 2 Pos, 25mA, 24VDC, SMD", CurrentRating_mA=25A, Manufacturer="CTS Electrocomponents", Supplier Part Number 1=CT2182LPST-ND
TP1 TP2 TP6 TP7: library part CMP-0003825-1, "1mm Test Point, SMT", Manufacturer=Any
TP3 TP4 TP5: "TEST POINT.  No entry in BOM.", Manufacturer=N/A
U1 U2 U4 U13 U14 U18 U24: library part CMP-0073613-3, "4-Channel Ultra-Low-Capacitance IEC ESD Protection Diode, DQA0010A (USON-10)", Alternate Manufacturer="Texas Instruments"
U3 U17 U22: library part CMP-0043093-4, "Single-Channel ESD in 0402 Package With 10pF Capacitance and 6V Breakdown, DPY0002A (X1SON-2)", Alternate Manufacturer="Texas Instruments", Alternate PartNumber=TPD1E10B06DPYT, Breakdown Voltage(Min)(V)=6, IO Capacitance(Typ)(pF)=10, Operating Temperature Range="-40 to 125 C", Rating=Catalog
U5: library part CMP-0073614-1, "6-Channel Ultra-Low-Capacitance IEC ESD Protection Diodes, RVZ0014A (USON-14)", Alternate Manufacturer="Texas Instruments"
